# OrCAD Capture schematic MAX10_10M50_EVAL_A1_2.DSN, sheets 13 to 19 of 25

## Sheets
13 MIPI CSI-2 Rx D-PHY OV5640: size A3; title: MAX 10 FPGA (10M50) Evaluation Kit
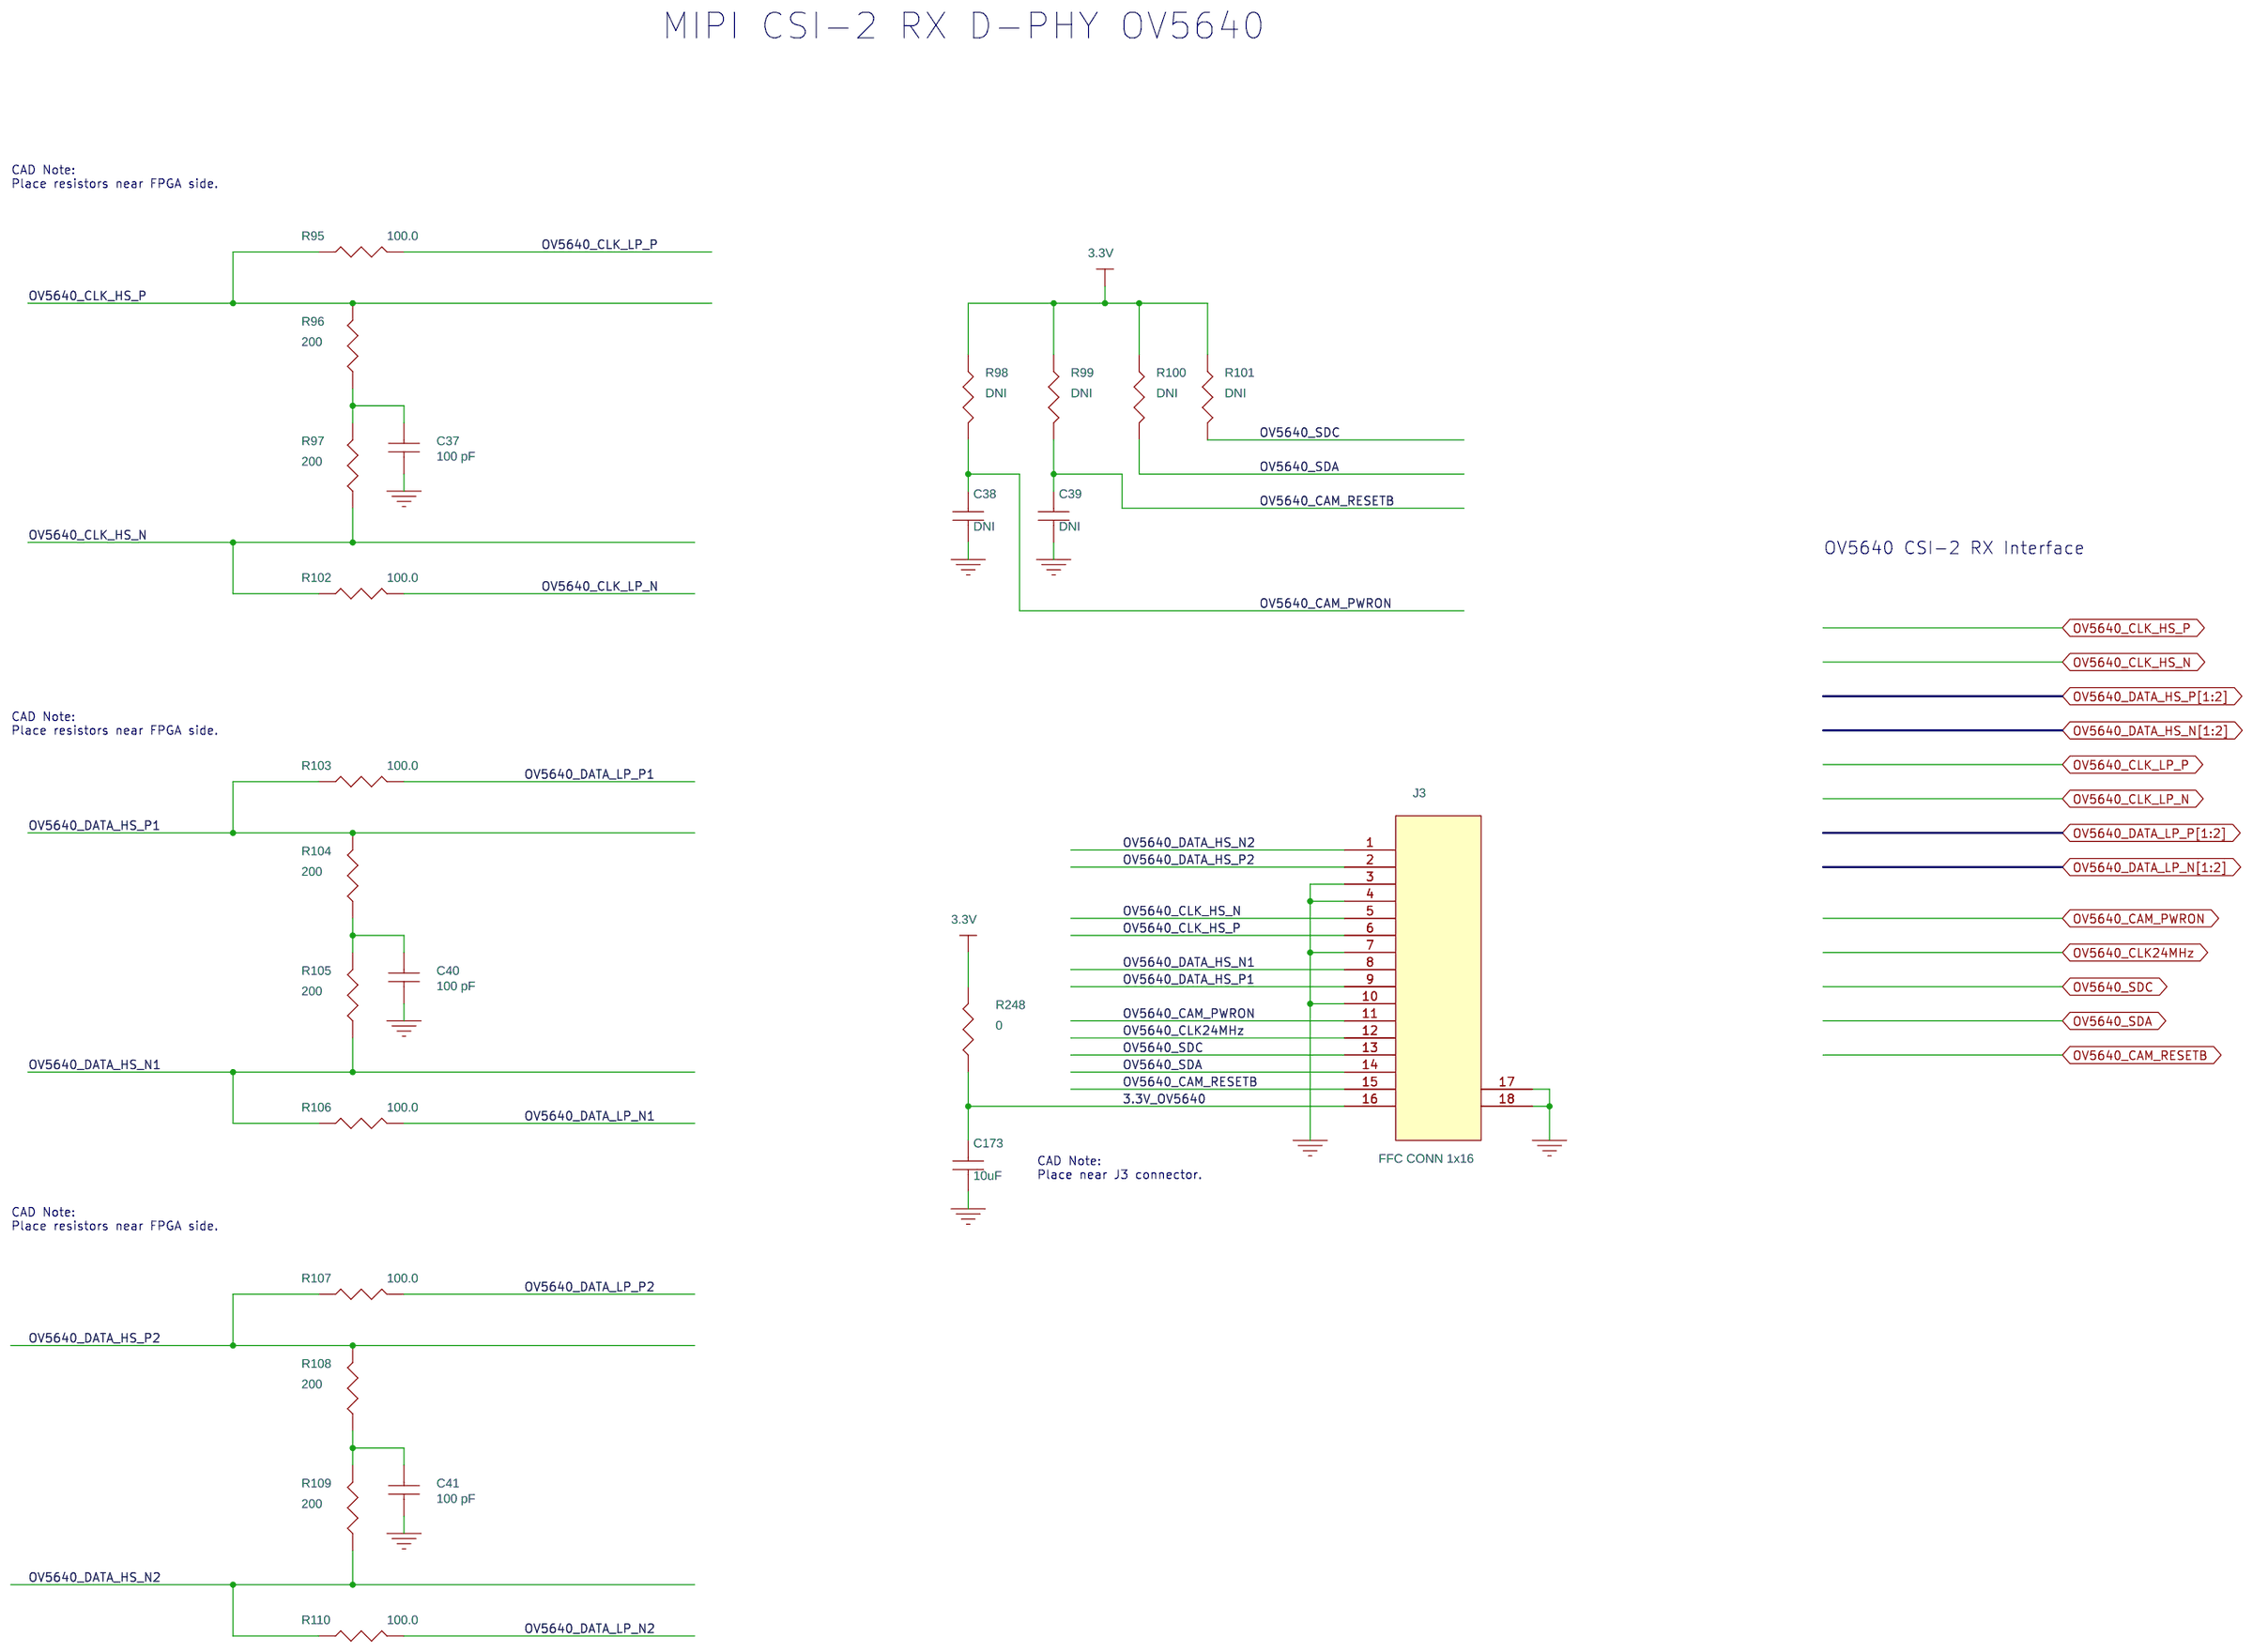
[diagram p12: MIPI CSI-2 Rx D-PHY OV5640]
14 HDMI (VIDEO ONLY): size A3
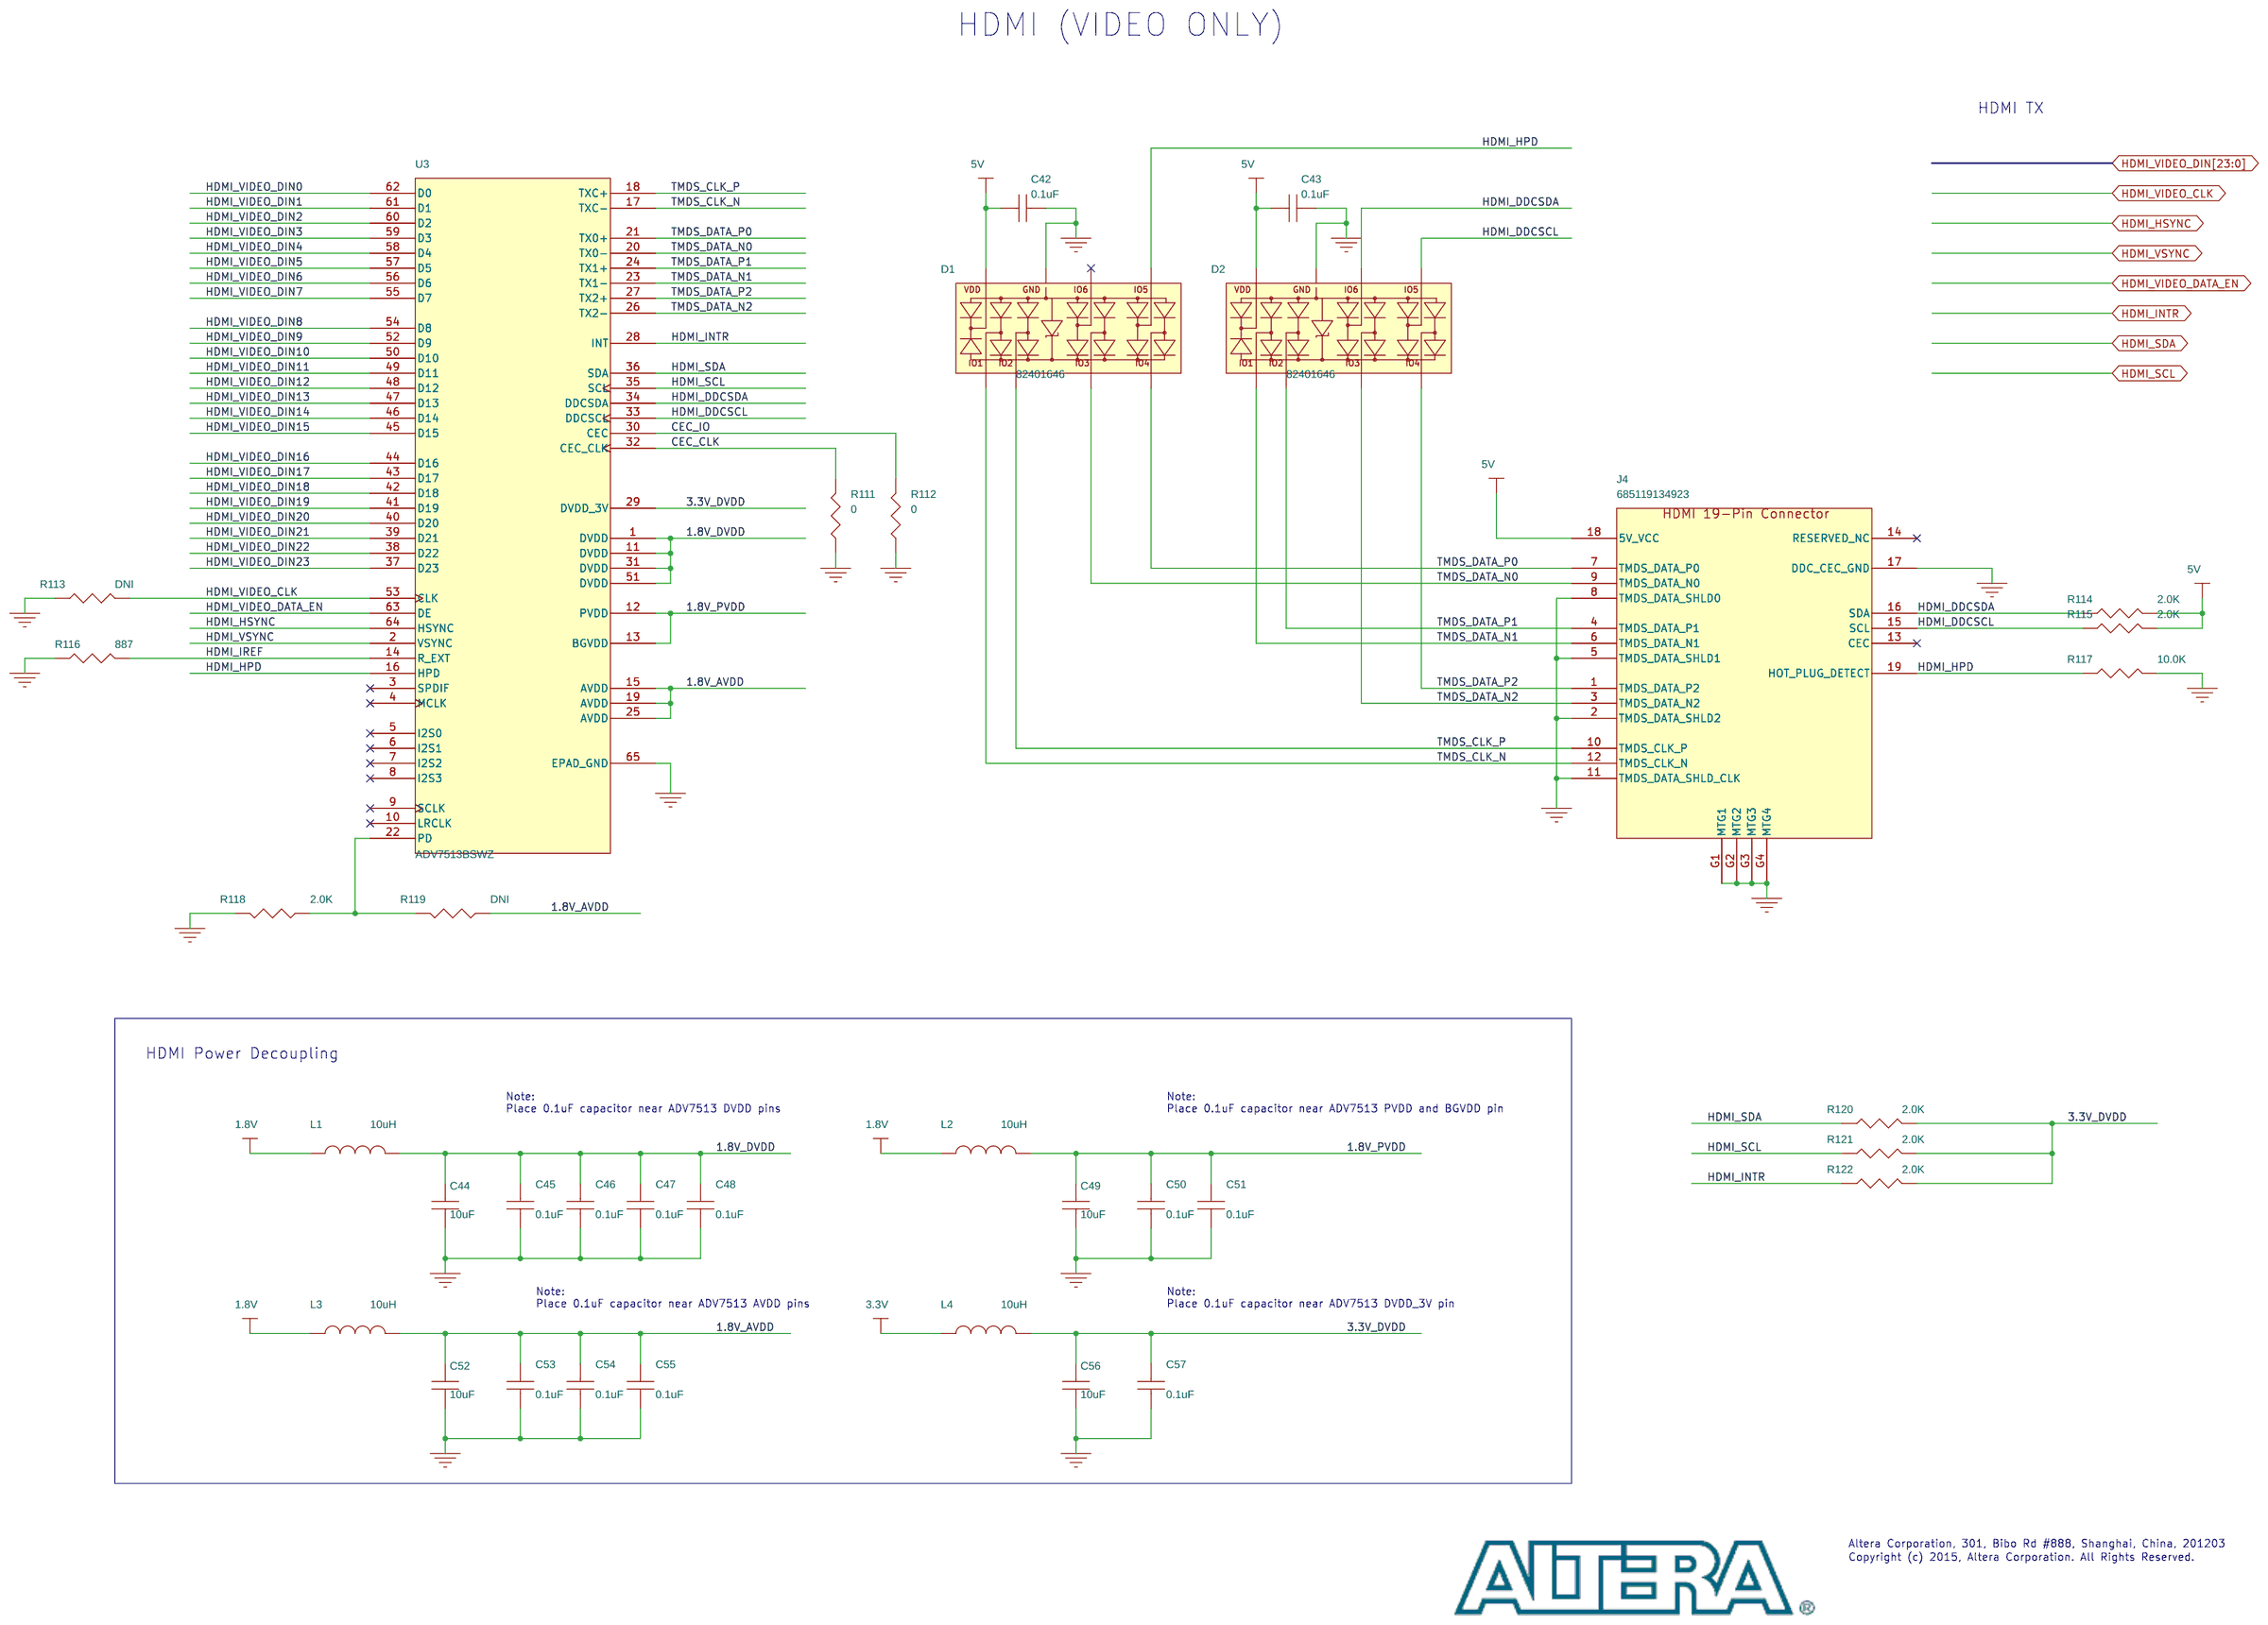
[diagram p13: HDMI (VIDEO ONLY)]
15 On-Board USB Blaster II -1: size A3
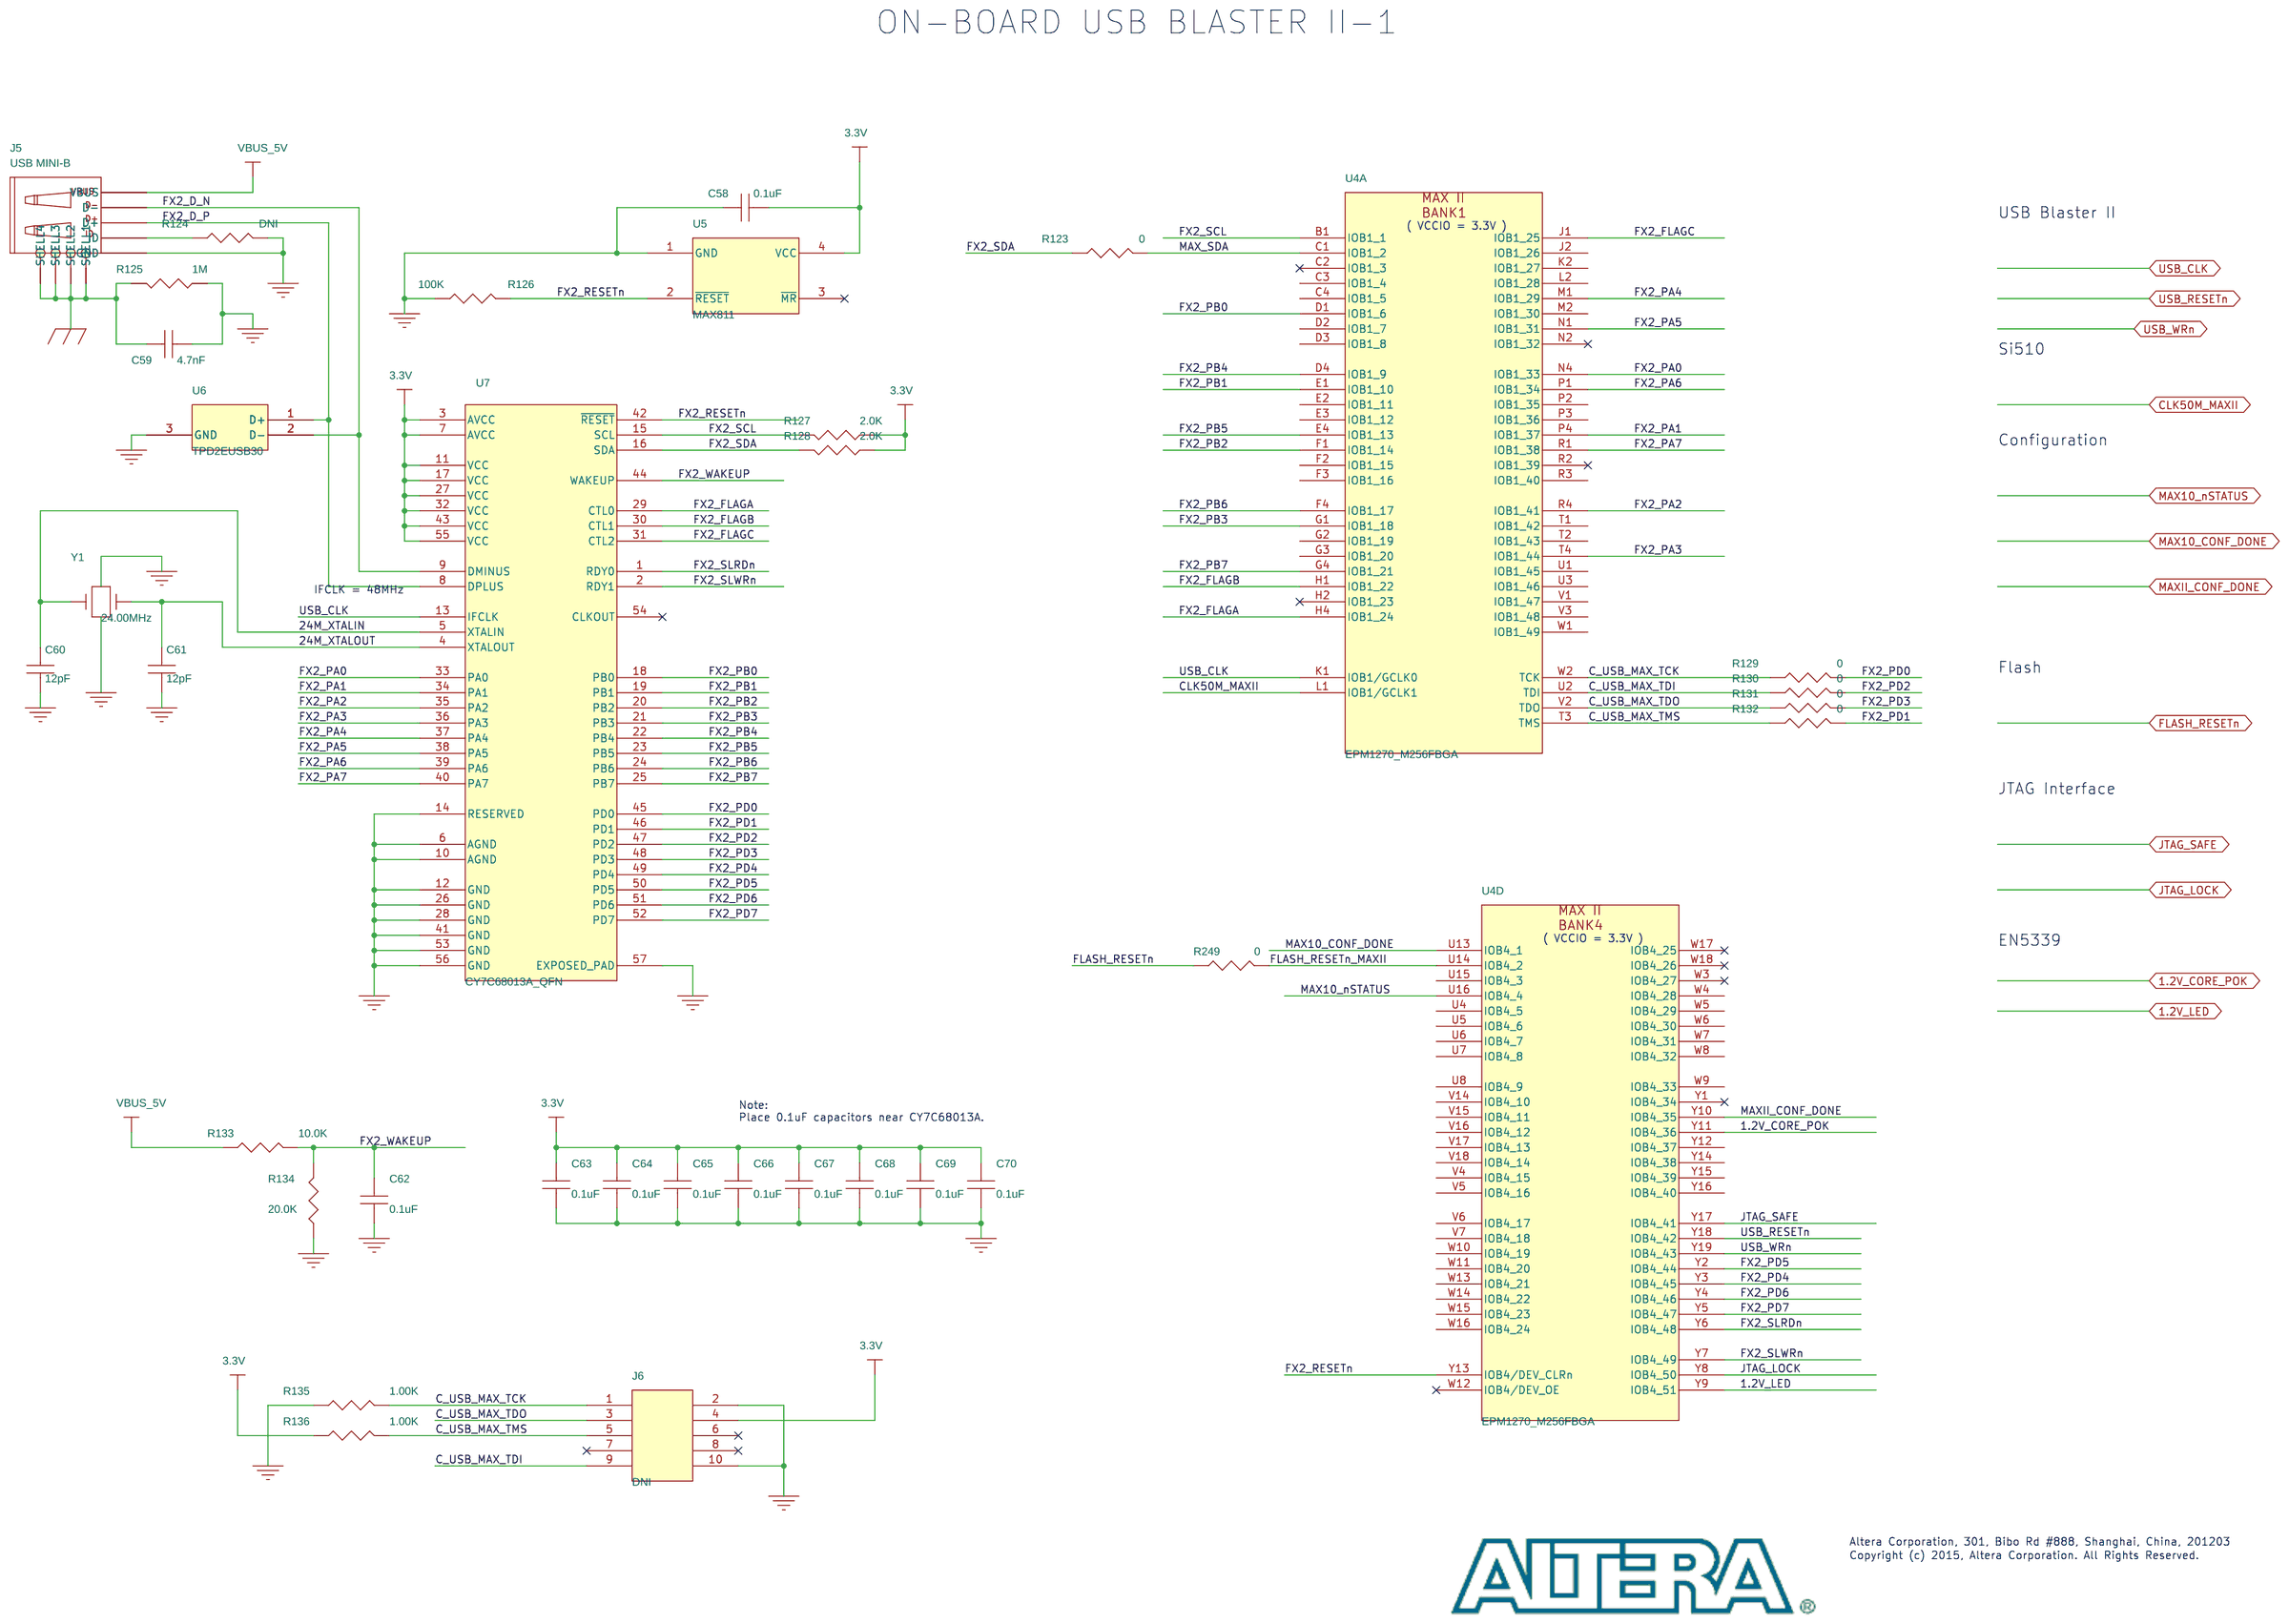
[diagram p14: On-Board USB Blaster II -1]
16 On-Board USB Blaster II-2: size A3
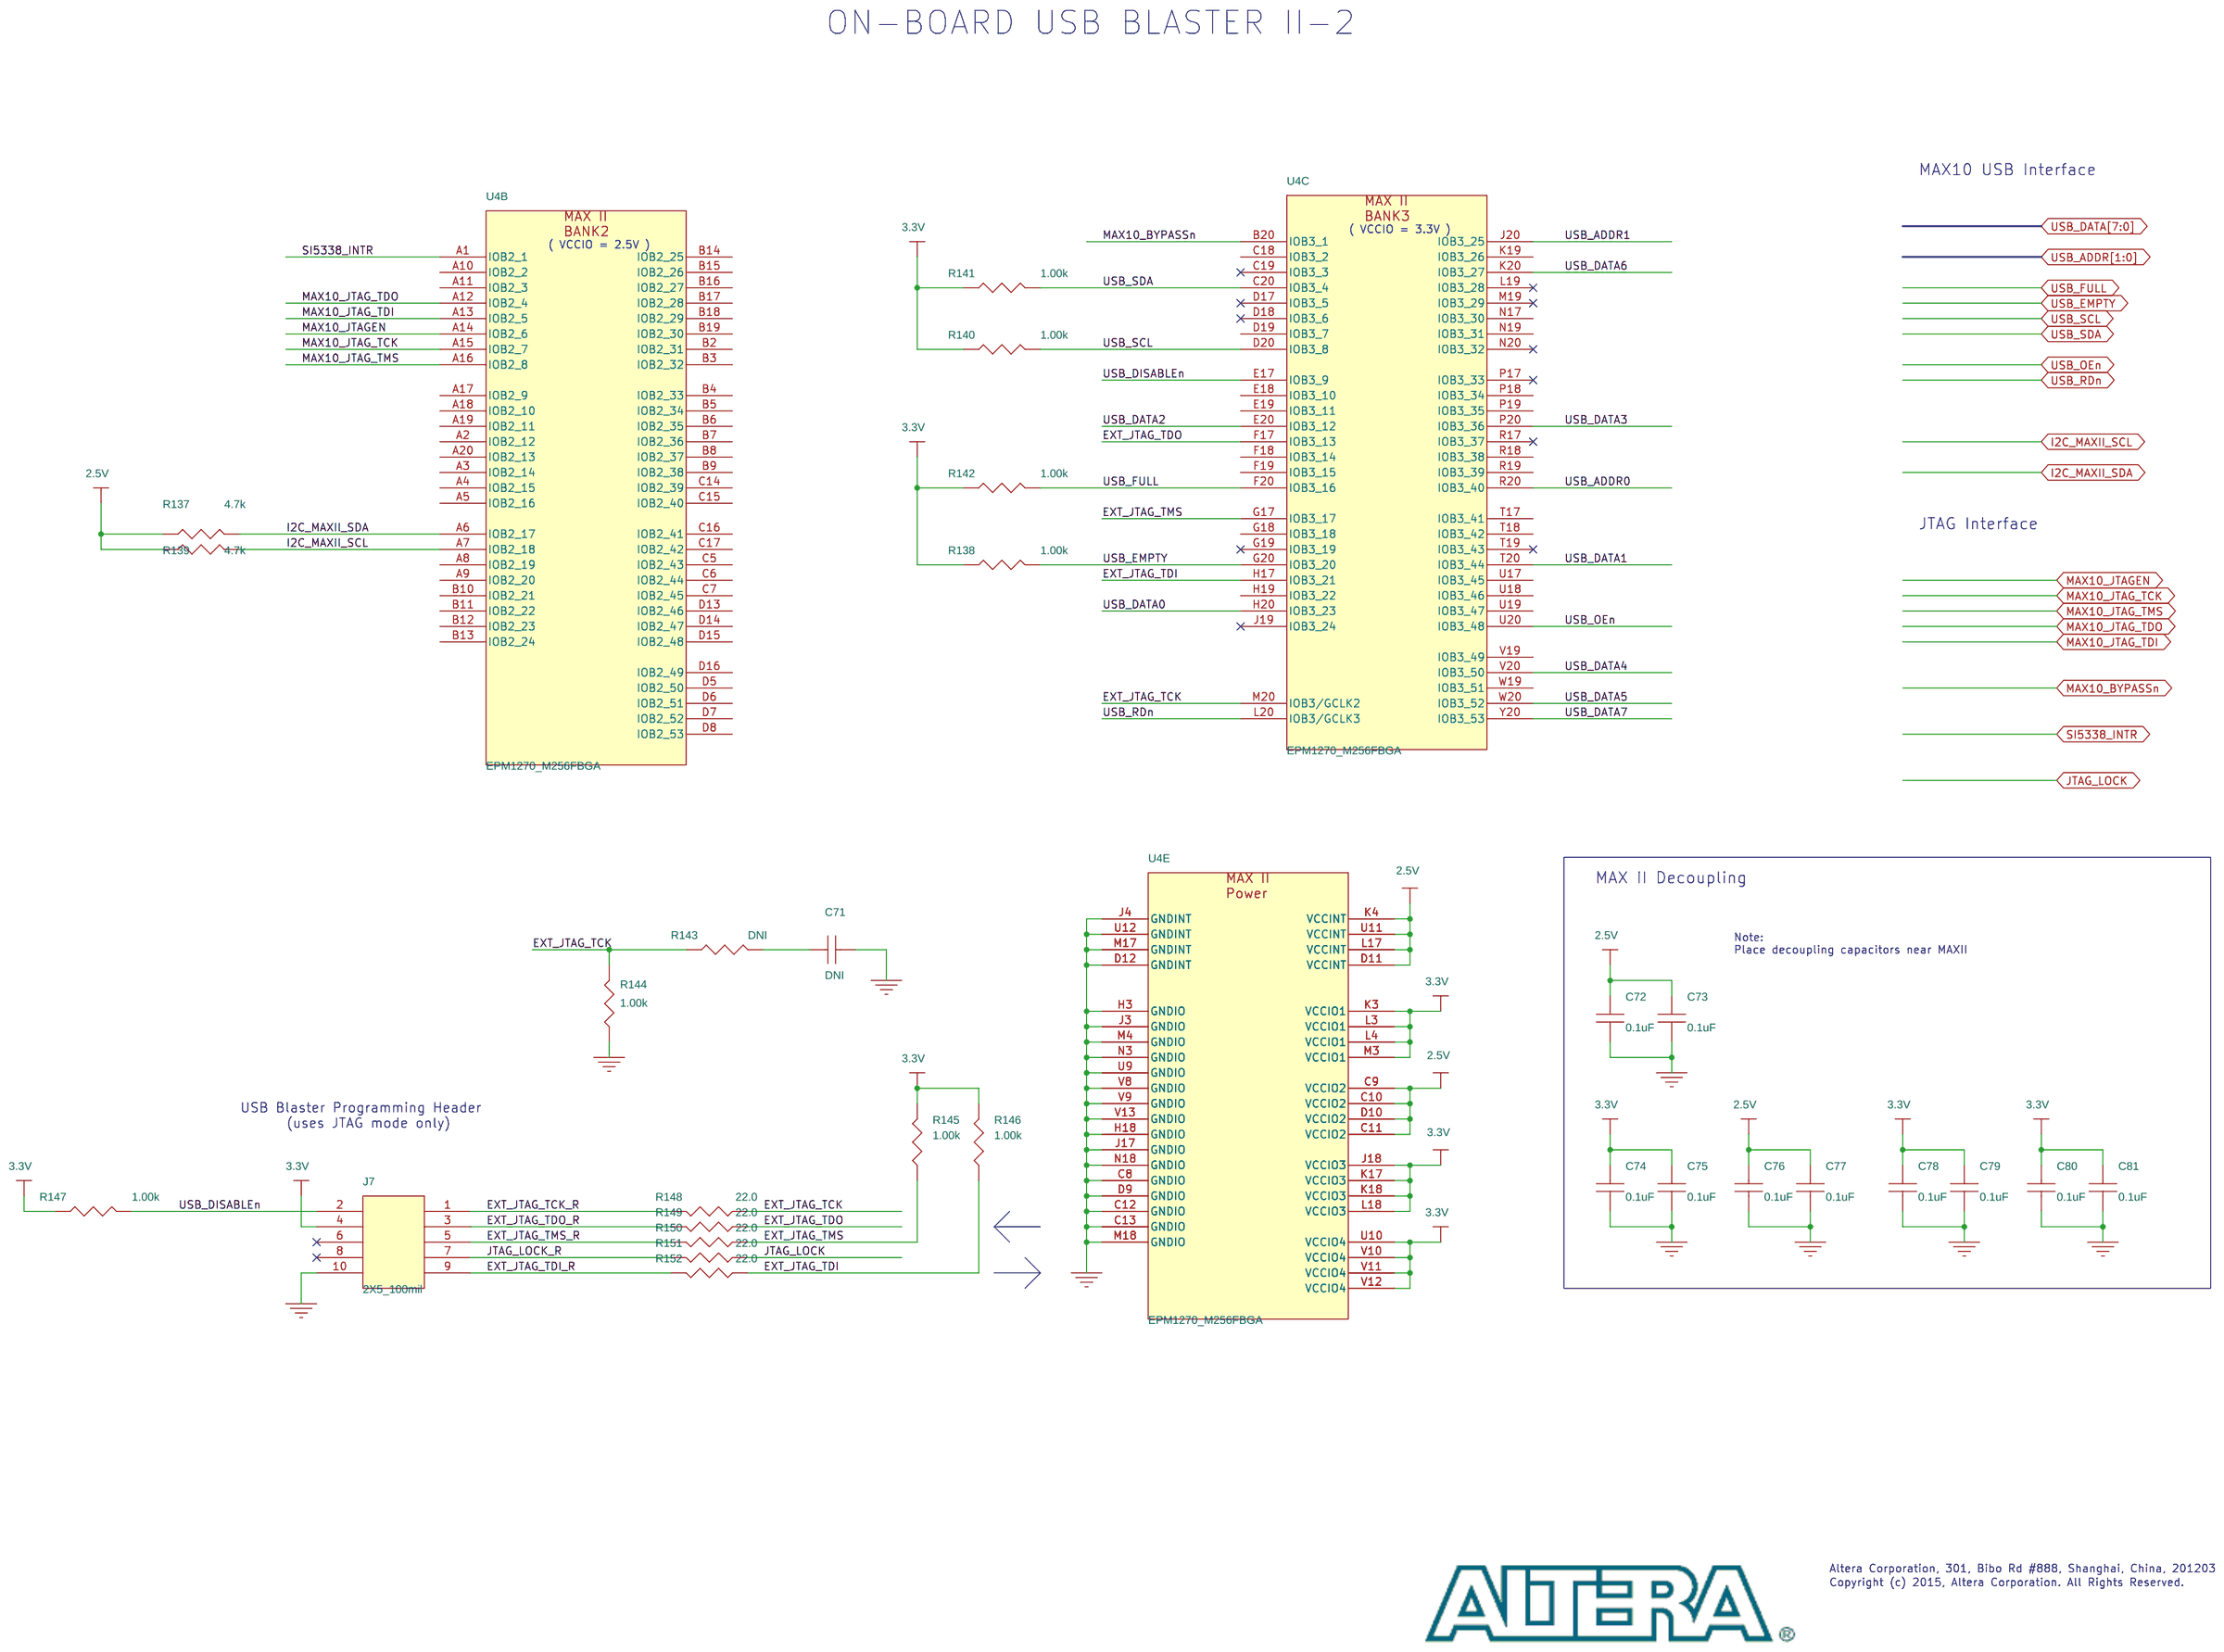
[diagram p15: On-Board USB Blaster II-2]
17 PMOD, GPIO, LVDS UserIO: size A3
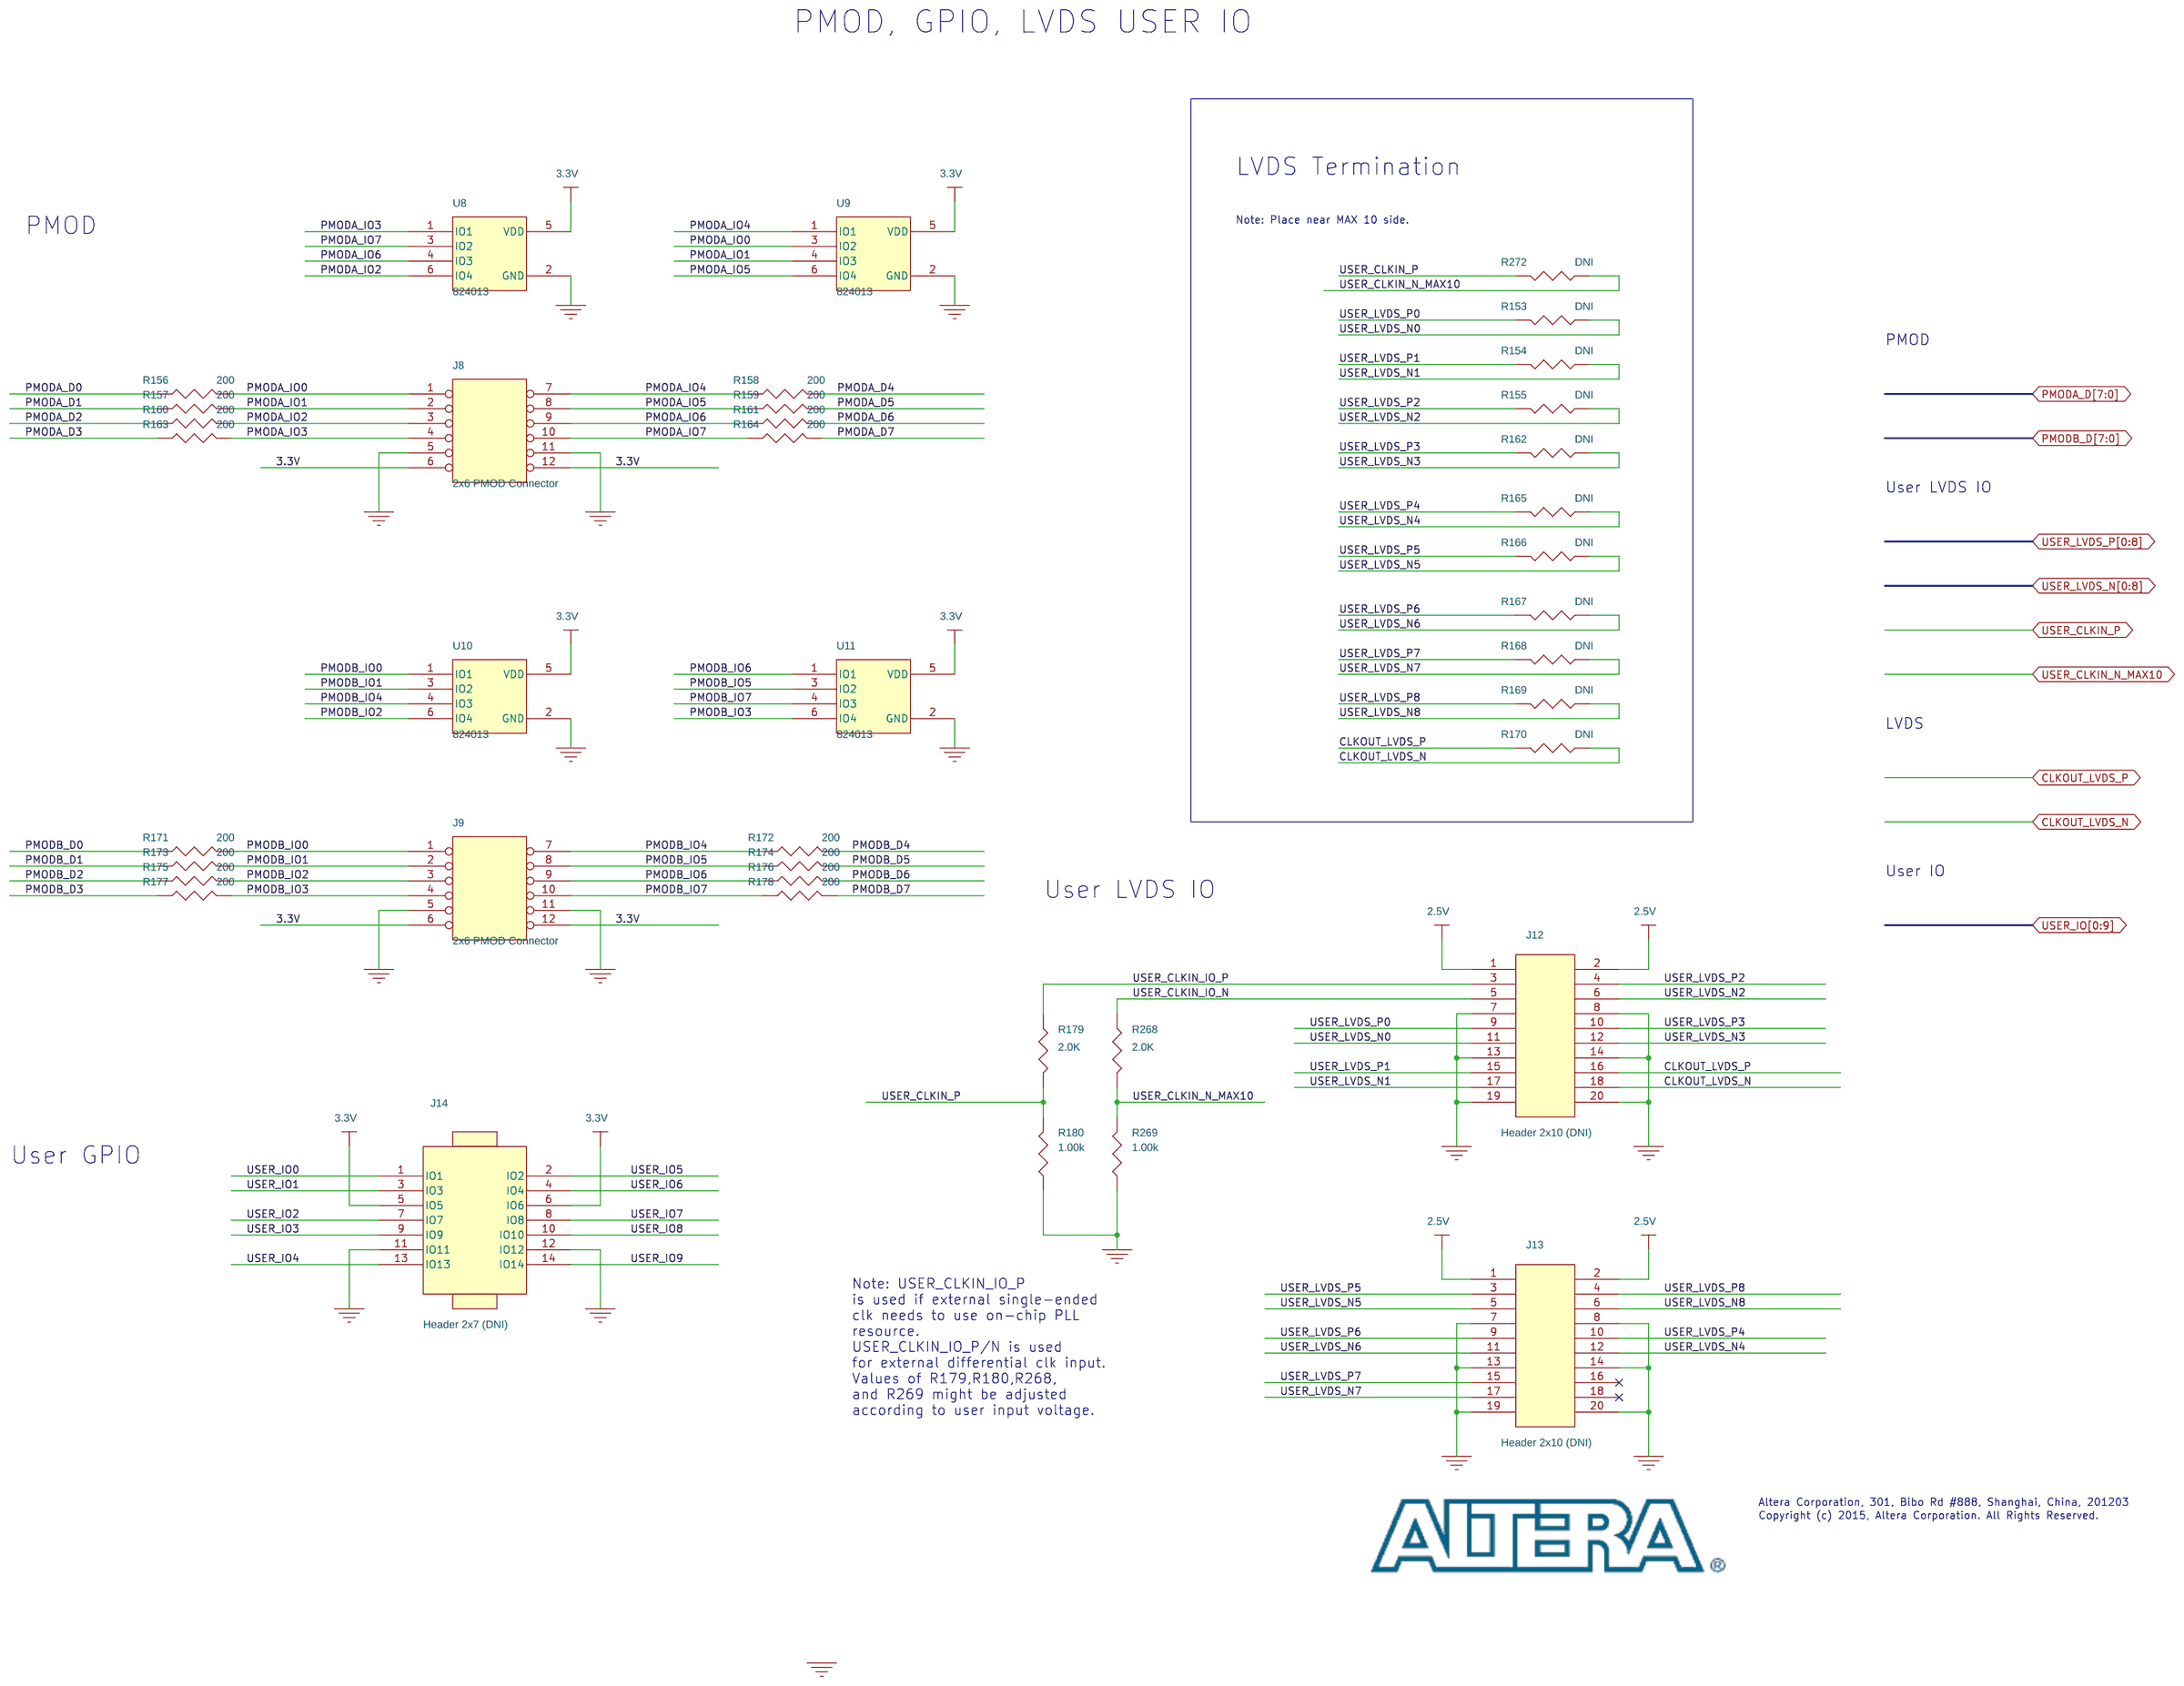
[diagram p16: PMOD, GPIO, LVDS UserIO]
18 Pushbutton, Switch, LED: size A3
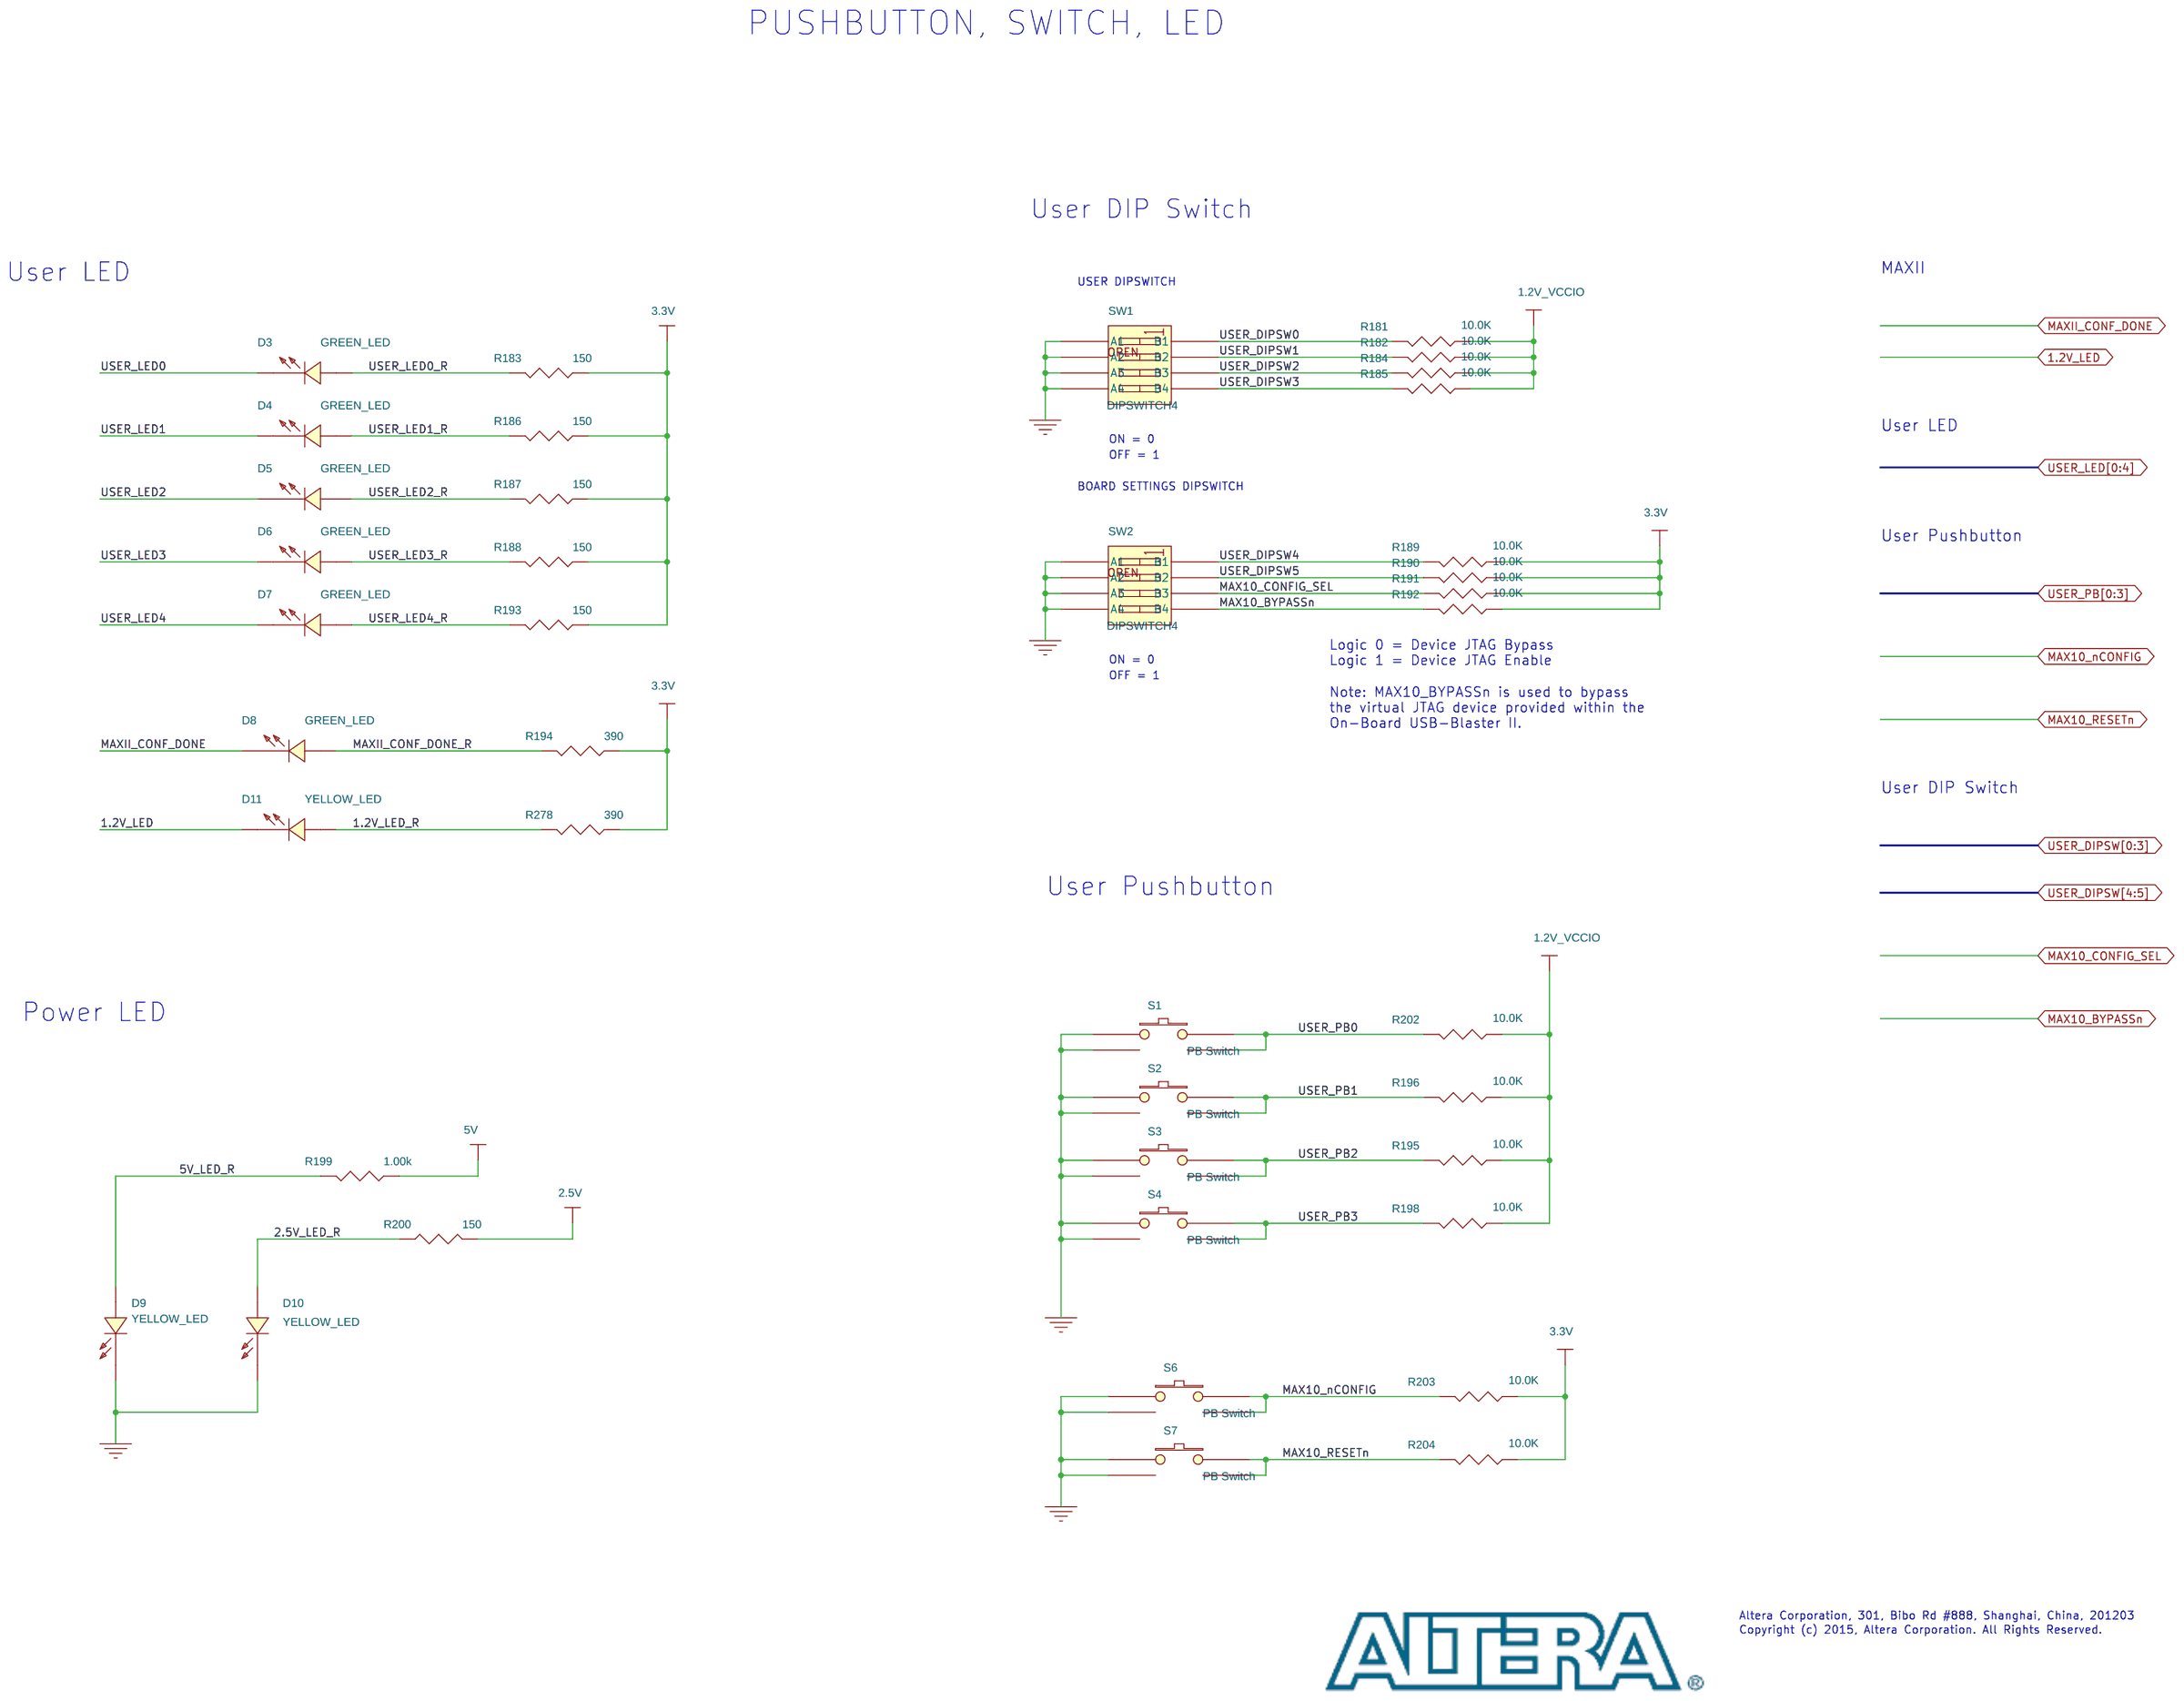
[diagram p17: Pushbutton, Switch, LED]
19 Clocking: size A3
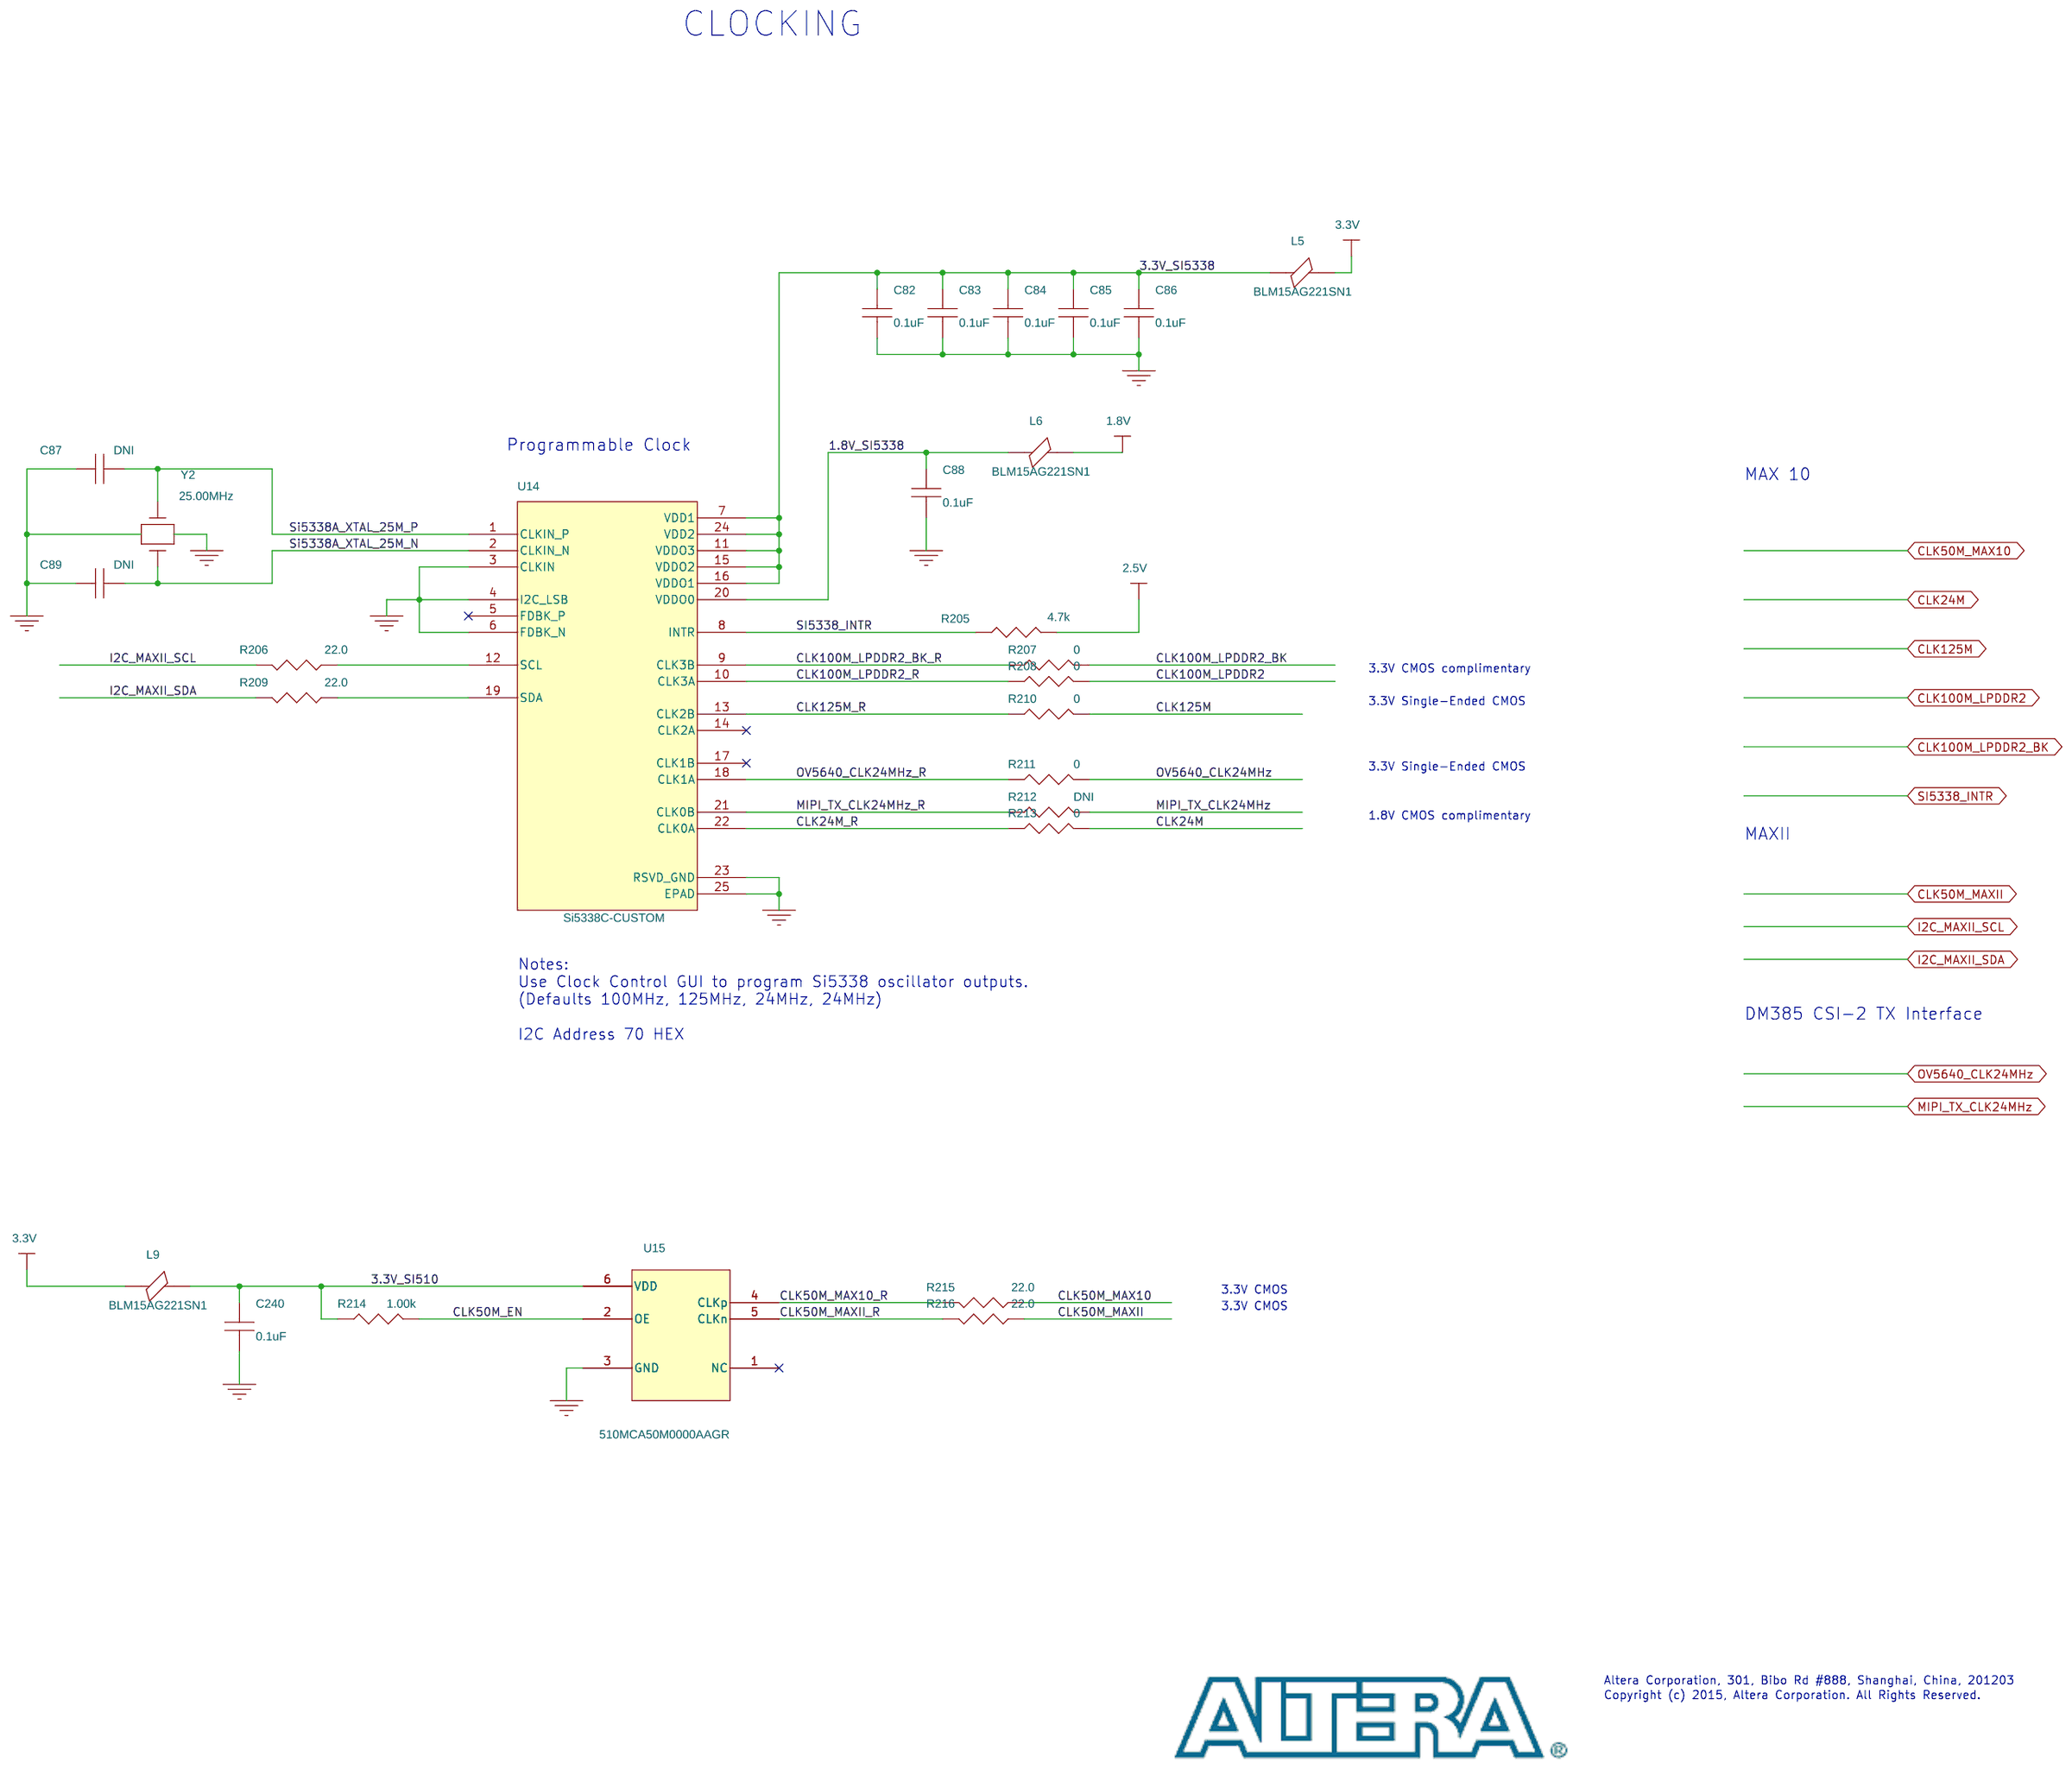
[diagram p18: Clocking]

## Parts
sheet Clocking
C82  0.1uF  [0402]
C83  0.1uF  [0402]
C84  0.1uF  [0402]
C85  0.1uF  [0402]
C86  0.1uF  [0402]
C87  DNI  [0402]
C88  0.1uF  [0402]
C89  DNI  [0402]
C240  0.1uF  [0402]
L5  BLM15AG221SN1  [0402]
L6  BLM15AG221SN1  [0402]
L9  BLM15AG221SN1  [0402]
R205  4.7k  [0402]
R206  22.0  [0402]
R207  0  [0402]
R208  0  [0402]
R209  22.0  [0402]
R210  0  [0402]
R211  0  [0402]
R212  DNI  [0402]
R213  0  [0402]
R214  1.00k  [0402]
R215  22.0  [0402]
R216  22.0  [0402]
U14  Si5338C-CUSTOM  [QFN24]
U15  510MCA50M0000AAGR  [si510]
Y2  25.00MHz  [XTAL_FA-128]
sheet HDMI (VIDEO ONLY)
C42  0.1uF  [0402]
C43  0.1uF  [0402]
C44  10uF  [0603]
C45  0.1uF  [0402]
C46  0.1uF  [0402]
C47  0.1uF  [0402]
C48  0.1uF  [0402]
C49  10uF  [0603]
C50  0.1uF  [0402]
C51  0.1uF  [0402]
C52  10uF  [0603]
C53  0.1uF  [0402]
C54  0.1uF  [0402]
C55  0.1uF  [0402]
C56  10uF  [0603]
C57  0.1uF  [0402]
D1  82401646  [wurth_msop8]
D2  82401646  [wurth_msop8]
J4  685119134923  [HDMI-19PIN]
L1  10uH  [0806]
L2  10uH  [0806]
L3  10uH  [0806]
L4  10uH  [0806]
R111  0  [0402]
R112  0  [0402]
R113  DNI  [0402]
R114  2.0K  [0402]
R115  2.0K  [0402]
R116  887  [0402]
R117  10.0K  [0402]
R118  2.0K  [0402]
R119  DNI  [0402]
R120  2.0K  [0402]
R121  2.0K  [0402]
R122  2.0K  [0402]
U3  ADV7513BSWZ  [LQFP-64]
sheet MIPI CSI-2 Rx D-PHY OV5640
C37  100 pF  [0402]
C38  DNI  [C0402_BGA]
C39  DNI  [C0402_BGA]
C40  100 pF  [0402]
C41  100 pF  [0402]
C173  10uF  [0603]
J3  FFC CONN 1x16  [68711614522]
R95  100.0  [0402]
R96  200  [0402]
R97  200  [0402]
R98  DNI  [0402]
R99  DNI  [0402]
R100  DNI  [0402]
R101  DNI  [0402]
R102  100.0  [0402]
R103  100.0  [0402]
R104  200  [0402]
R105  200  [0402]
R106  100.0  [0402]
R107  100.0  [0402]
R108  200  [0402]
R109  200  [0402]
R110  100.0  [0402]
R248  0  [0402]
sheet On-Board USB Blaster II -1
C58  0.1uF  [0402]
C59  4.7nF  [0402]
C60  12pF  [0402]
C61  12pF  [0402]
C62  0.1uF  [0402]
C63  0.1uF  [0402]
C64  0.1uF  [0402]
C65  0.1uF  [0402]
C66  0.1uF  [0402]
C67  0.1uF  [0402]
C68  0.1uF  [0402]
C69  0.1uF  [0402]
C70  0.1uF  [0402]
J5  USB MINI-B  [Wurth_USB_MINI-B]
J6  DNI  [hdr2x5_100mil_smt]
R123  0  [0402]
R124  DNI  [0402]
R125  1M  [0402]
R126  100K  [0402]
R127  2.0K  [0402]
R128  2.0K  [0402]
R129  0  [0402]
R130  0  [0402]
R131  0  [0402]
R132  0  [0402]
R133  10.0K  [0402]
R134  20.0K  [0402]
R135  1.00K  [0402]
R136  1.00K  [0402]
R249  0  [0402]
U5  MAX811  [SOT-143]
U6  TPD2EUSB30  [DRT]
U7  CY7C68013A_QFN  [QFN56]
Y1  24.00MHz  [XTAL_FA-128]
sheet On-Board USB Blaster II-2
C71  DNI  [0402]
C72  0.1uF  [0402]
C73  0.1uF  [0402]
C74  0.1uF  [0402]
C75  0.1uF  [0402]
C76  0.1uF  [0402]
C77  0.1uF  [0402]
C78  0.1uF  [0402]
C79  0.1uF  [0402]
C80  0.1uF  [0402]
C81  0.1uF  [0402]
J7  2X5_100mil  [hdr2x5_100mil_smt]
R137  4.7k  [0402]
R138  1.00k  [0402]
R139  4.7k  [0402]
R140  1.00k  [0402]
R141  1.00k  [0402]
R142  1.00k  [0402]
R143  DNI  [0402]
R144  1.00k  [0402]
R145  1.00k  [0402]
R146  1.00k  [0402]
R147  1.00k  [0402]
R148  22.0  [0402]
R149  22.0  [0402]
R150  22.0  [0402]
R151  22.0  [0402]
R152  22.0  [0402]
U4  EPM1270_M256FBGA  [M256]  (sections A,B,C,D,E)
sheet PMOD, GPIO, LVDS UserIO
J8  2x6 PMOD Connector  [HDR2X6_100MIL]
J9  2x6 PMOD Connector  [HDR2X6_100MIL]
J12  Header 2x10 (DNI)  [10-89-1201]
J13  Header 2x10 (DNI)  [10-89-1201]
J14  Header 2x7 (DNI)  [10-89-1141]
R153  DNI  [0402]
R154  DNI  [0402]
R155  DNI  [0402]
R156  200  [0402]
R157  200  [0402]
R158  200  [0402]
R159  200  [0402]
R160  200  [0402]
R161  200  [0402]
R162  DNI  [0402]
R163  200  [0402]
R164  200  [0402]
R165  DNI  [0402]
R166  DNI  [0402]
R167  DNI  [0402]
R168  DNI  [0402]
R169  DNI  [0402]
R170  DNI  [0402]
R171  200  [0402]
R172  200  [0402]
R173  200  [0402]
R174  200  [0402]
R175  200  [0402]
R176  200  [0402]
R177  200  [0402]
R178  200  [0402]
R179  2.0K  [0402]
R180  1.00k  [0402]
R268  2.0K  [0402]
R269  1.00k  [0402]
R272  DNI  [0402]
U8  824013  [SOT23-6L]
U9  824013  [SOT23-6L]
U10  824013  [SOT23-6L]
U11  824013  [SOT23-6L]
sheet Pushbutton, Switch, LED
D3  GREEN_LED  [LED_0603]
D4  GREEN_LED  [LED_0603]
D5  GREEN_LED  [LED_0603]
D6  GREEN_LED  [LED_0603]
D7  GREEN_LED  [LED_0603]
D8  GREEN_LED  [LED_0603]
D9  YELLOW_LED  [LED_0603]
D10  YELLOW_LED  [LED_0603]
D11  YELLOW_LED  [LED_0603]
R181  10.0K  [0402]
R182  10.0K  [0402]
R183  150  [0402]
R184  10.0K  [0402]
R185  10.0K  [0402]
R186  150  [0402]
R187  150  [0402]
R188  150  [0402]
R189  10.0K  [0402]
R190  10.0K  [0402]
R191  10.0K  [0402]
R192  10.0K  [0402]
R193  150  [0402]
R194  390  [0402]
R195  10.0K  [0402]
R196  10.0K  [0402]
R198  10.0K  [0402]
R199  1.00k  [0402]
R200  150  [0402]
R202  10.0K  [0402]
R203  10.0K  [0402]
R204  10.0K  [0402]
R278  390  [0402]
S1  PB Switch  [pushbutton_smt]
S2  PB Switch  [pushbutton_smt]
S3  PB Switch  [pushbutton_smt]
S4  PB Switch  [pushbutton_smt]
S6  PB Switch  [pushbutton_smt]
S7  PB Switch  [pushbutton_smt]
SW1  DIPSWITCH4  [DIPSWITCH_SMT_QUAD]
SW2  DIPSWITCH4  [DIPSWITCH_SMT_QUAD]

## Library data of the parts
C42 C43 C45-C48 C50 C51 C53-C55 C57 C58 C62-C86 C88 C240 = Cap_0.1UF_+_-10%_10V_0402
C87 C89 = Cap_18PF_5%_50V_0402
L5 L6 L9 = IND_Ferrite_0402_300mA_220
R137 R139 R205 = RES_4.7k_OHM_5%_1_16W_0402: RES - 4.7K OHMS, 5%, 1/16W,0402
R148-R152 R206 R209 R215 R216 = RESISTOR: RES - 22.0 OHM, 1/16W, 1%, 0402 SMD; Item Num: P02-16269R; Lead Free Status: Yes; Manufacturer: Panasonic; Manufacturer Part Num: ERJ-2RKF22R0X; Num Pins: 2; Part Class: Resistors; Price: 0
R111 R112 R123 R129-R132 R207 R208 R210 R211 R213 R248 R249 = RESISTOR: RES ZERO OHM 1/16W 5% 0402 SMD; Altera Part No.: P02-14020R; Item Num: P02-14020R; Lead Free Status: No; Manufacturer: Panasonic; Manufacturer Part Num: ERJ-2GE0R00X; Num Pins: 2; Part Class: RESISTORS; RoHS Compliant: Yes; Tolerance: 5%
R124 R212 = RESISTOR: RES ZERO OHM 1/16W 5% 0402 SMD; Altera Part No.: P02-14020R; Item Num: P02-14020R; Lead Free Status: No; Manufacturer: Panasonic; Manufacturer Part Num: ERJ-2GE0R00X; Num Pins: 2; Part Class: RESISTORS; Price: 0; RoHS Compliant: Yes; Tolerance: 5%
R138 R140-R142 R144-R147 R180 R199 R214 R269 = RESISTOR: RES,1.00K OHMS,1.0%,1/16W,0402; Item Num: P02-11372R; Lead Free Status: No; Manufacturer: Panasonic; Manufacturer Part Num: ERJ-2RKF1001X; Num Pins: 2; Part Class: Resistors
U14 = Clock_Gen,_Si5338A_CUSTOM,_A5SK: IC - PROG,1.8V, 3.3V CMOS QUAD CLOCK, 24M, 24M, 125M, 100M DEFAULTS, I2C 70; Item Num: P13-27236R; Manufacturer Part Num: Si5338C-B04601-GM
U15 = Si510-DualCMOS: OSC - 50MHZ, +/-30PPM, 3.3V, DUAL CMOS (IN PHASE), CRYSTAL OSCILLATOR, SMD; Item Num: P13-27235R; Manufacturer: Silicon Labs
Y2 = XTAL_25MHz_30PPM_18pF_mini
C44 C49 C52 C56 C173 = CAP: CAP - CERAMIC, 10UF, 6.3V, +/-20%, X5R, 0603 SMD; AGILE_LINK: http://sj-agile9app/Agile/PLMServlet?action=OpenEmailObject&classid=10000&objid=260383822; Item Num: P03-16323R; LIFECYCLE_PHASE: Active; Lead Free Status: Lead Free; MFR_LIFECYCLE: Active; Manufacturer: Panasonic; Manufacturer Part Num: ECJ-1VB0J106M; Num Pins: 2; PART_SUBCLASS: CAPACITORS; RATED_VOLTAGE: 6.3V; RoHS Compliant: RoHS Compliant; TOLERANCE: +/-20%
D1 D2 = 82401646: DIODE - ULTRA LOW CAPACITANCE ESD ARRAY, 0.3PF IO TO GND, 0.05PF IO TO IO, MSOP-8L; Item Num: P08-20757R; Lead Free Status: Yes; Manufacturer: Wurth; Num Pins: 8; RoHS Compliant: Yes
J4 = HDMI_19-Pin_Receptacle: CONN-HDMI RECEPTABLE; Item Num: P23-38479R; Manufacturer: Wurth Elektronik
L1-L4 = IND_10uH_245mA_0.82ohm_0806_SMD
R113 = R: RES, 49.9 OHMS, 1%, 1/16W, 0402; Item Num: P02-14101R; Lead Free Status: Yes; Manufacturer: NIC Components Corp.; Manufacturer Part Num: NRC04F49R9TRF; Num Pins: 2; Part Class: Resistors; Price: 0
R114 R115 R118-R122 R127 R128 R179 R268 = RES_2.0K_OHM_1_16W_1%_0402_SMD
R116 = R: RES - 887 OHM, 1%, 1/16W, 0402 SMD; AGILE_LINK: http://sj-agile9app/Agile/PLMServlet?action=OpenEmailObject&classid=10000&objid=259725586; Item Num: P02-15629R; LIFECYCLE_PHASE: Preliminary; Lead Free Status: Lead Free; MFR_LIFECYCLE: Active; Manufacturer: Panasonic; Manufacturer Part Num: ERJ-2RKF8870x; Num Pins: 2; PART_SUBCLASS: RESISTORS; RoHS Compliant: RoHS Compliant
R117 R133 R181 R182 R184 R185 R189-R192 R195 R196 R198 R202-R204 = RESISTOR: RES,10.0K OHMS,1.0%,1/16W, 0402; AGILE_LINK: http://sj-agile9app/Agile/PLMServlet?action=OpenEmailObject&classid=10000&objid=146548997; Item Num: P02-11364R; LIFECYCLE_PHASE: Active; Lead Free Status: No; MFR_LIFECYCLE: Active; Manufacturer: Panasonic; Manufacturer Part Num: ERJ-2RKF1002X; Num Pins: 2; PART_SUBCLASS: RESISTORS; POWER: 1/16W; RoHS Compliant: Yes; TOLERANCE: +/-1%
U3 = ADV7513BSWZ: IC TX HDMI 165MHZ 64LQFP; Item Num: P01-17910R; Manufacturer: Analog Devices Inc
C37 C40 C41 = Cap_0.1UF_+_-10%_10V_0402: CAP, CERAMIC, 100PF, 10%, 50V, 0402, X7R; Item Num: P03-15133R; Manufacturer Part Num: ECJ-0EB1H101K
C38 C39 = CAP_1.0UF_10%_10V_0402
J3 = FFC_CONN_0: CONN FPC HORIZONTAL 16POS 0.5mm SMT ZIF, Bottom Contact; Item Num: P23-38696R; Manufacturer: Wurth Electronics
R95 R102 R103 R106 R107 R110 R153-R155 R162 R165-R170 R272 = RES_100_OHM_1.0%_1_16W_0402: RES,100OHMS, 1.0%, 1/16W, 0402
R96 R97 R104 R105 R108 R109 R156-R161 R163 R164 R171-R178 = RESISTOR: RES,200 OHMS,1.0%,1/16W,0402; Item Num: P02-10716R; Lead Free Status: Yes; Manufacturer: Panasonic; Manufacturer Part Num: ERJ-2RKF2000X; Num Pins: 2; Part Class: Resistors; Price: 0; RoHS Compliant: Yes
R98-R101 = RES_2.0K_OHM_1_16W_1%_0402_SMD: RES 2.2K OHM 1/16W 5% 0402 SMD; Item Num: P02-14027R; Manufacturer Part Num: ERJ-2GEJ222X
C59 = Cap_4.7nF_10%_50V_0402: CAP 4700PF 25V CERAMIC 0402 SMD ±10% X7R; Item Num: P03-16476R; Manufacturer: Panasonic; Manufacturer Part Num: ECJ-0EB1E472K
C60 C61 = CAP: CAP - 12PF, 50V, +/-5%, CERAMIC, 0402 SMD; AGILE_LINK: http://sj-agile9app/Agile/PLMServlet?action=OpenEmailObject&classid=10000&objid=257385742; Item Num: P03-15352R; LIFECYCLE_PHASE: Active; Lead Free Status: Lead Free; MFR_LIFECYCLE: Active; Manufacturer: Panasonic; Manufacturer Part Num: ECJ-0EC1H120J; Num Pins: 2; PART_SUBCLASS: CAPACITORS; RATED_VOLTAGE: 50V; RoHS Compliant: RoHS Compliant; TOLERANCE: +/-5%
J5 = USB_MINI-B: CONN - MINI USB 5POS HORIZ T/H; Item Num: P23-38638R; Manufacturer: Wurth Elektronik; Manufacturer Part Num: 651 005 136 521
J6 J7 = 2x5: CONN - CONN HEADER VERT DUAL 10POS 2.54MM; Item Num: P23-38640R; Lead Free Status: No; Manufacturer: Wurth Elektronik; Manufacturer Part Num: 61001021121; Num Pins: 10; Part Class: Connectors; Price: 0; RoHS Compliant: Yes
R125 = RESISTOR: RES 1.00M OHM 1/16W 1% 0402 SMD; Item Num: P02-14034R; LIFECYCLE_PHASE: Active; Lead Free Status: Lead Free; MFR_LIFECYCLE: Active; Manufacturer: Panasonic; Manufacturer Part Num: ERJ-2RKF1004X; Num Pins: 2; Package: SMD; RoHS Compliant: RoHS Compliant; TOLERANCE: +/-1%
R126 = RESISTOR: RES,100K OHMS,1.0%,1/16W,0402; Item Num: P02-11386R; Lead Free Status: No; Manufacturer: Panasonic; Manufacturer Part Num: ERJ-2RKF1003X; Num Pins: 2; Part Class: Resistors; Price: 0; RoHS Compliant: Yes
R134 = RESISTOR: RES 20.0K OHM 1/16W 1% 0402 SMD; Item Num: P02-14071R; Lead Free Status: Yes; Manufacturer: Panasonic; Manufacturer Part Num: ERJ-2RKF2002X; Num Pins: 2; Part Class: RESISTORS; RoHS Compliant: Yes
R135 R136 = RESISTOR: RES,1.00K OHMS,1.0%,1/16W,0402; Item Num: P02-11372R; Lead Free Status: No; Manufacturer: Panasonic; Manufacturer Part Num: ERJ-2RKF1001X; Num Pins: 2; Part Class: Resistors; Price: 0
U5 = MAX811: IC - MPU V-MONITOR 2.93V, RESET/POWER-ON RESET, SOT143-4; Item Num: P01-17588R; Lead Free Status: Yes; Manufacturer: Maxim Integrated Products; Manufacturer Part Num: MAX811SEUS+T; Num Pins: 4; Part Class: ICs; RoHS Compliant: Yes
U6 = TPD2EUSB30: DIODE - FULL SPEED USB ESD SOLUTION, 2CH, SOT3; Item Num: P08-20777R; Lead Free Status: Yes; MFR_LIFECYCLE: Active; Manufacturer: Texas Instruments; Manufacturer Part Num: TPD2EUSB30DRxx; Num Pins: 3; Part Class: ICS; RoHS Compliant: Yes
U7 = CY7C68013A_56QFN: IC - EZ-USB FX2LP Microcontroller 400KHz, 56-QFN, 3.3V; Item Num: P01-17739R; Lead Free Status: Yes; Manufacturer: Cypress; Manufacturer Part Num: CY7C68013A-56LTXCx; Num Pins: 57; Part Class: ICs; RoHS Compliant: Yes
Y1 = CRYSTAL_SM_13: CRYSTAL - MINI XTL, 24.00 MHZ, +/-50PPM, +/-30PPM-20~75C, 12PF, 2.0mm x 1.6mm SMD; Item Num: P07-19648R; Lead Free Status: Yes; MFR_LIFECYCLE: Active; Manufacturer: Epson Toyocom; Manufacturer Part Num: FA-128 24.0000MB-W:; Num Pins: 4; RoHS Compliant: Yes
R143 = RESISTOR: RES,10.0K OHMS,1.0%,1/16W, 0402; AGILE_LINK: http://sj-agile9app/Agile/PLMServlet?action=OpenEmailObject&classid=10000&objid=146548997; Item Num: P02-11364R; LIFECYCLE_PHASE: Active; Lead Free Status: No; MFR_LIFECYCLE: Active; Manufacturer: Panasonic; Manufacturer Part Num: ERJ-2RKF1002X; Num Pins: 2; PART_SUBCLASS: RESISTORS; POWER: 1/16W; RESISTANCE: 10.0K; RoHS Compliant: Yes; TOLERANCE: +/-1%
U4 = EPM1270M256_2: IC - MAX II EPM1270 256-MBGA, 2.5V/3.3V VCCINT; Item Num: P01-17848R; LIFECYCLE_PHASE: Preliminary; Lead Free Status: Lead Free; MFR_LIFECYCLE: Active; Manufacturer: Altera Corporation; Manufacturer Part Num: EPM1270M256C4N; Num Pins: 256; PART_SUBCLASS: ICS; RoHS Compliant: RoHS Compliant
J8 J9 = 2x6_PMOD: CONN - HEADER 2X6CONN HEADER - 12 POS, 2.54MM ANGLED DUAL SOCKET HEADER WR-PHD, 0.1", TH LEADS 0.1", LEAD LENGTH 0.230"; Item Num: P23-38635R; Manufacturer: Wurth Elektronik; Manufacturer Part Num: 613012243121
J12 J13 = 2x10: CONN - CONN HEADER VERT DUAL 20POS 2.54; Item Num: P23-38639R; Manufacturer: Wurth Elektronik; Manufacturer Part Num: 61302021121; Mfr Code: MOL; Num Pins: 20; Part Class: CON; RoHS Compliant: 1
J14 = Header_3: CONN - CONN HEADER VERT DUAL 14POS 2.54; Item Num: P23-38701R; Manufacturer Part Num: 61301421121
U8-U11 = 824013: DIODE - TVS DIODE, HIGH SPEED SERIES, 3.3VWM 6VC SOT23; Item Num: P08-20832R; Manufacturer: Wurth Elektronik
D3-D8 = LED_WURTH_1: LED - BRIGHT GREEN, VF=2V, IF=0.03A, 0603; Item Num: P09-21344R; LIFECYCLE_PHASE: Active; Lead Free Status: Lead Free; Manufacturer: Wurth Electroniks; Manufacturer Part Num: 150060VS75000; Num Pins: 2; PART_SUBCLASS: LEDS; Part Class: LEDS; RoHS Compliant: RoHS Compliant
D9-D11 = LED_WURTH_1: LED -YELLOW, VF=2V, IF=0.03A, 0603; Item Num: P09-21346R; LIFECYCLE_PHASE: Active; Lead Free Status: Lead Free; Manufacturer: Wurth Electroniks; Manufacturer Part Num: 150060YS75000; Num Pins: 2; PART_SUBCLASS: LEDS; Part Class: LEDS; RoHS Compliant: RoHS Compliant
R183 R186-R188 R193 R200 = R: RES, 150 OHM, 5%, 1/16W, 0402; Item Num: P02-14145R; Lead Free Status: No; Manufacturer: Panasonic; Manufacturer Part Num: ERJ-2GEJ151X; Num Pins: 2; Part Class: Resistors; Price: 0; RoHS Compliant: Yes
R194 R278 = R: RES, 390 Ohms, 5%, 1/16W, 0402; Item Num: P02-14109R; Manufacturer: Panasonic; Manufacturer Part Num: ERJ-2GEJ391X; Num Pins: 2; Part Class: Resistors; Price: 0; RoHS Compliant: Yes
S1-S4 S6 S7 = TS-A02SA-2-S100: SWITCH - PUSHBUTTON, SPST, SMD; Item Num: P11-24535R; Lead Free Status: No; Manufacturer: Wurth Elektronik; Manufacturer Part Num: 430181038816; Num Pins: 4; Part Class: Switches; RoHS Compliant: Yes
SW1 SW2 = SPST4: SWITCHES - 4 POS, 8 PIN, Ultra-mini SMT Half-pitch Slider DIP Switch; AGILE_LINK: http://sj-agile9app/Agile/PLMServlet?action=OpenEmailObject&classid=10000&objid=258073635; Item Num: P11-24098R; LIFECYCLE_PHASE: Preliminary; Lead Free Status: Not Lead Free; MFR_LIFECYCLE: Active; Manufacturer: Wurth Electronik; Manufacturer Part Num: 416131160804; Num Pins: 8; PART_SUBCLASS: SWITCHES; RoHS Compliant: RoHS Compliant

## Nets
1.2V_CORE_POK: U4.Y11(IOB4_36) ; also on sheet 22
1.2V_LED: D11.2(CATHODE) U4.Y9(IOB4_51)
1.2V_LED_R: D11.1(ANODE) R278.2
1.2V_VCCIO: R181.1 R182.1 R184.1 R185.1 R195.1 R196.1 R198.1 R202.1 ; also on sheet 6 10 22 23 24
1.8V: L1.1 L2.1 L3.1 L6.2 ; also on sheet 4 10 11 12 20 21 22 23 24
1.8V_AVDD: C52.1 C53.1 C54.1 C55.1 L3.2 R119.1 U3.15(AVDD) U3.19(AVDD) U3.25(AVDD)
1.8V_DVDD: C44.1 C45.1 C46.1 C47.1 C48.1 L1.2 U3.1(DVDD) U3.11(DVDD) U3.31(DVDD) U3.51(DVDD)
1.8V_PVDD: C49.1 C50.1 C51.1 L2.2 U3.12(PVDD) U3.13(BGVDD)
1.8V_SI5338: C88.1 L6.1 U14.20(VDDO0)
2.5V: C72.1 C73.1 C76.1 C77.1 J12.1 J12.2 J13.1 J13.2 R137.1 R139.1 R200.2 R205.2 U4.C9(VCCIO2) U4.C10(VCCIO2) U4.C11(VCCIO2) U4.D10(VCCIO2) U4.D11(VCCINT) U4.K4(VCCINT) U4.L17(VCCINT) U4.U11(VCCINT) ; also on sheet 9 21 22 23 24
2.5V_LED_R: D10.1(ANODE) R200.1
3.3V: C58.2 C63.1 C64.1 C65.1 C66.1 C67.1 C68.1 C69.1 C70.1 C74.1 C75.1 C78.1 C79.1 C80.1 C81.1 J6.4 J7.4 J8.6 J8.12 J9.6 J9.12 J14.5(IO5) J14.6(IO6) L4.1 L5.2 L9.1 R98.1 R99.1 R100.1 R101.1 R127.1 R128.1 R136.1 R138.1 R140.1 R141.1 R142.1 R145.2 R146.2 R147.1 R183.1 R186.1 R187.1 R188.1 R189.1 R190.1 R191.1 R192.1 R193.1 R194.1 R203.1 R204.1 R248.2 R278.1 U4.J18(VCCIO3) U4.K3(VCCIO1) U4.K17(VCCIO3) U4.K18(VCCIO3) U4.L3(VCCIO1) U4.L4(VCCIO1) U4.L18(VCCIO3) U4.M3(VCCIO1) U4.U10(VCCIO4) U4.V10(VCCIO4) U4.V11(VCCIO4) U4.V12(VCCIO4) U5.4(VCC) U7.3(AVCC) U7.7(AVCC) U7.11(VCC) U7.17(VCC) U7.27(VCC) U7.32(VCC) U7.43(VCC) U7.55(VCC) U8.5(VDD) U9.5(VDD) U10.5(VDD) U11.5(VDD) ; also on sheet 9 11 12 20 22 23 24 25
3.3V_DVDD: C56.1 C57.1 L4.2 R120.2 R121.2 R122.2 U3.29(DVDD_3V)
3.3V_OV5640: C173.1 J3.16 R248.1
3.3V_SI510: C240.1 L9.2 R214.1 U15.6(VDD)
3.3V_SI5338: C82.1 C83.1 C84.1 C85.1 C86.1 L5.1 U14.7(VDD1) U14.11(VDDO3) U14.15(VDDO2) U14.16(VDDO1) U14.24(VDD2)
5V: C42.1 C43.1 D1.8 D2.8 J4.18(5V_VCC) R114.2 R115.2 R199.1 ; also on sheet 20 21 22
5V_LED_R: D9.1(ANODE) R199.2
GND: C37.2 C38.2 C39.2 C40.2 C41.2 C42.2 C43.2 C44.2 C45.2 C46.2 C47.2 C48.2 C49.2 C50.2 C51.2 C52.2 C53.2 C54.2 C55.2 C56.2 C57.2 C58.1 C59.2 C60.2 C61.2 C62.2 C63.2 C64.2 C65.2 C66.2 C67.2 C68.2 C69.2 C70.2 C71.2 C72.2 C73.2 C74.2 C75.2 C76.2 C77.2 C78.2 C79.2 C80.2 C81.2 C82.2 C83.2 C84.2 C85.2 C86.2 C87.1 C88.2 C89.1 C173.2 C240.2 D1.7 D2.7 D9.2(CATHODE) D10.2(CATHODE) J3.3 J3.4 J3.7 J3.10 J3.17 J3.18 J4.2(TMDS_DATA_SHLD2) J4.5(TMDS_DATA_SHLD1) J4.8(TMDS_DATA_SHLD0) J4.11(TMDS_DATA_SHLD_CLK) J4.17(DDC_CEC_GND) J4.G1(MTG1) J4.G2(MTG2) J4.G3(MTG3) J4.G4(MTG4) J5.5(GND) J6.2 J6.10 J7.10 J8.5 J8.11 J9.5 J9.11 J12.7 J12.8 J12.13 J12.14 J12.19 J12.20 J13.7 J13.8 J13.13 J13.14 J13.19 J13.20 J14.11(IO11) J14.12(IO12) R111.1 R112.1 R113.1 R116.1 R117.2 R118.2 R124.2 R125.1 R126.2 R134.1 R135.1 R144.1 R180.1 R269.1 S1.1 S1.2 S2.1 S2.2 S3.1 S3.2 S4.1 S4.2 S6.1 S6.2 S7.1 S7.2 SW1.1(A1) SW1.2(A2) SW1.3(A3) SW1.4(A4) SW2.1(A1) SW2.2(A2) SW2.3(A3) SW2.4(A4) U3.65(EPAD_GND) U4.C8(GNDIO) U4.C12(GNDIO) U4.C13(GNDIO) U4.D9(GNDIO) U4.D12(GNDINT) U4.H3(GNDIO) U4.H18(GNDIO) U4.J3(GNDIO) U4.J4(GNDINT) U4.J17(GNDIO) U4.M4(GNDIO) U4.M17(GNDINT) U4.M18(GNDIO) U4.N3(GNDIO) U4.N18(GNDIO) U4.U9(GNDIO) U4.U12(GNDINT) U4.V8(GNDIO) U4.V9(GNDIO) U4.V13(GNDIO) U5.1(GND) U6.3(GND) U7.6(AGND) U7.10(AGND) U7.12(GND) U7.14(RESERVED) U7.26(GND) U7.28(GND) U7.41(GND) U7.53(GND) U7.56(GND) U7.57(EXPOSED_PAD) U8.2(GND) U9.2(GND) U10.2(GND) U11.2(GND) U14.3(CLKIN) U14.4(I2C_LSB) U14.6(FDBK_N) U14.23(RSVD_GND) U14.25(EPAD) U15.3(GND) Y1.2 Y1.4 Y2.2 Y2.4 ; also on sheet 4 6 8 9 10 11 12 20 21 22 23 24 25
GND_EARTH: C59.1 J5.6(SHELL1) J5.7(SHELL2) J5.8(SHELL3) J5.9(SHELL4) R125.2
VBUS_5V: J5.1(VBUS) R133.1 ; also on sheet 20
24M_XTALIN: C60.1 U7.5(XTALIN) Y1.1
24M_XTALOUT: C61.1 U7.4(XTALOUT) Y1.3
C_USB_MAX_TCK: J6.1 R129.1 R135.2 U4.W2(TCK)
C_USB_MAX_TDI: J6.9 R130.1 U4.U2(TDI)
C_USB_MAX_TDO: J6.3 R131.1 U4.V2(TDO)
C_USB_MAX_TMS: J6.5 R132.1 R136.2 U4.T3(TMS)
CEC_CLK: R111.2 U3.32(CEC_CLK)
CEC_IO: R112.2 U3.30(CEC)
CLK24M: R213.2 ; also on sheet 8
CLK24M_R: R213.1 U14.22(CLK0A)
CLK50M_EN: R214.2 U15.2(OE)
CLK50M_MAX10: R215.2 ; also on sheet 8
CLK50M_MAX10_R: R215.1 U15.4(CLKp)
CLK50M_MAXII: R216.2 U4.L1(IOB1/GCLK1)
CLK50M_MAXII_R: R216.1 U15.5(CLKn)
CLK100M_LPDDR2: R208.2 ; also on sheet 8
CLK100M_LPDDR2_BK: R207.2 ; also on sheet 8
CLK100M_LPDDR2_BK_R: R207.1 U14.9(CLK3B)
CLK100M_LPDDR2_R: R208.1 U14.10(CLK3A)
CLK125M: R210.2 ; also on sheet 8
CLK125M_R: R210.1 U14.13(CLK2B)
CLKOUT_LVDS_N: J12.18 R170.1 ; also on sheet 8
CLKOUT_LVDS_P: J12.16 R170.2 ; also on sheet 8
EXT_JTAG_TCK: R143.1 R144.2 R148.2 U4.M20(IOB3/GCLK2)
EXT_JTAG_TCK_R: J7.1 R148.1
EXT_JTAG_TDI: R146.1 R152.2 U4.H17(IOB3_21)
EXT_JTAG_TDI_R: J7.9 R152.1
EXT_JTAG_TDO: R149.2 U4.F17(IOB3_13)
EXT_JTAG_TDO_R: J7.3 R149.1
EXT_JTAG_TMS: R145.1 R150.2 U4.G17(IOB3_17)
EXT_JTAG_TMS_R: J7.5 R150.1
FLASH_RESETn: R249.1 ; also on sheet 7 25
FLASH_RESETn_MAXII: R249.2 U4.U14(IOB4_2)
FX2_D_N: J5.2(D-) U6.2(D-) U7.9(DMINUS)
FX2_D_P: J5.3(D+) U6.1(D+) U7.8(DPLUS)
FX2_FLAGA: U4.H4(IOB1_24) U7.29(CTL0)
FX2_FLAGB: U4.H1(IOB1_22) U7.30(CTL1)
FX2_FLAGC: U4.J1(IOB1_25) U7.31(CTL2)
FX2_PA0: U4.N4(IOB1_33) U7.33(PA0)
FX2_PA1: U4.P4(IOB1_37) U7.34(PA1)
FX2_PA2: U4.R4(IOB1_41) U7.35(PA2)
FX2_PA3: U4.T4(IOB1_44) U7.36(PA3)
FX2_PA4: U4.M1(IOB1_29) U7.37(PA4)
FX2_PA5: U4.N1(IOB1_31) U7.38(PA5)
FX2_PA6: U4.P1(IOB1_34) U7.39(PA6)
FX2_PA7: U4.R1(IOB1_38) U7.40(PA7)
FX2_PB0: U4.D1(IOB1_6) U7.18(PB0)
FX2_PB1: U4.E1(IOB1_10) U7.19(PB1)
FX2_PB2: U4.F1(IOB1_14) U7.20(PB2)
FX2_PB3: U4.G1(IOB1_18) U7.21(PB3)
FX2_PB4: U4.D4(IOB1_9) U7.22(PB4)
FX2_PB5: U4.E4(IOB1_13) U7.23(PB5)
FX2_PB6: U4.F4(IOB1_17) U7.24(PB6)
FX2_PB7: U4.G4(IOB1_21) U7.25(PB7)
FX2_PD0: R129.2 U7.45(PD0)
FX2_PD1: R132.2 U7.46(PD1)
FX2_PD2: R130.2 U7.47(PD2)
FX2_PD3: R131.2 U7.48(PD3)
FX2_PD4: U4.Y3(IOB4_45) U7.49(PD4)
FX2_PD5: U4.Y2(IOB4_44) U7.50(PD5)
FX2_PD6: U4.Y4(IOB4_46) U7.51(PD6)
FX2_PD7: U4.Y5(IOB4_47) U7.52(PD7)
FX2_RESETn: R126.1 U4.Y13(IOB4/DEV_CLRn) U5.2(~{RESET}) U7.42(~{RESET})
FX2_SCL: R127.2 U4.B1(IOB1_1) U7.15(SCL)
FX2_SDA: R123.1 R128.2 U7.16(SDA)
FX2_SLRDn: U4.Y6(IOB4_48) U7.1(RDY0)
FX2_SLWRn: U4.Y7(IOB4_49) U7.2(RDY1)
FX2_WAKEUP: C62.1 R133.2 R134.2 U7.44(WAKEUP)
HDMI_DDCSCL: D2.5 J4.15(SCL) R115.1 U3.33(DDCSCL)
HDMI_DDCSDA: D2.6 J4.16(SDA) R114.1 U3.34(DDCSDA)
HDMI_HPD: D1.5 J4.19(HOT_PLUG_DETECT) R117.1 U3.16(HPD)
HDMI_HSYNC: U3.64(HSYNC) ; also on sheet 7
HDMI_INTR: R122.1 U3.28(INT) ; also on sheet 7
HDMI_IREF: R116.2 U3.14(R_EXT)
HDMI_SCL: R121.1 U3.35(SCL) ; also on sheet 7
HDMI_SDA: R120.1 U3.36(SDA) ; also on sheet 7
HDMI_VIDEO_CLK: R113.2 U3.53(CLK) ; also on sheet 8
HDMI_VIDEO_DATA_EN: U3.63(DE) ; also on sheet 7
HDMI_VIDEO_DIN0: U3.62(D0) ; also on sheet 7
HDMI_VIDEO_DIN1: U3.61(D1) ; also on sheet 7
HDMI_VIDEO_DIN2: U3.60(D2) ; also on sheet 7
HDMI_VIDEO_DIN3: U3.59(D3) ; also on sheet 7
HDMI_VIDEO_DIN4: U3.58(D4) ; also on sheet 7
HDMI_VIDEO_DIN5: U3.57(D5) ; also on sheet 7
HDMI_VIDEO_DIN6: U3.56(D6) ; also on sheet 7
HDMI_VIDEO_DIN7: U3.55(D7) ; also on sheet 7
HDMI_VIDEO_DIN8: U3.54(D8) ; also on sheet 7
HDMI_VIDEO_DIN9: U3.52(D9) ; also on sheet 7
HDMI_VIDEO_DIN10: U3.50(D10) ; also on sheet 7
HDMI_VIDEO_DIN11: U3.49(D11) ; also on sheet 7
HDMI_VIDEO_DIN12: U3.48(D12) ; also on sheet 7
HDMI_VIDEO_DIN13: U3.47(D13) ; also on sheet 7
HDMI_VIDEO_DIN14: U3.46(D14) ; also on sheet 7
HDMI_VIDEO_DIN15: U3.45(D15) ; also on sheet 7
HDMI_VIDEO_DIN16: U3.44(D16) ; also on sheet 7
HDMI_VIDEO_DIN17: U3.43(D17) ; also on sheet 7
HDMI_VIDEO_DIN18: U3.42(D18) ; also on sheet 7
HDMI_VIDEO_DIN19: U3.41(D19) ; also on sheet 7
HDMI_VIDEO_DIN20: U3.40(D20) ; also on sheet 7
HDMI_VIDEO_DIN21: U3.39(D21) ; also on sheet 7
HDMI_VIDEO_DIN22: U3.38(D22) ; also on sheet 7
HDMI_VIDEO_DIN23: U3.37(D23) ; also on sheet 7
HDMI_VSYNC: U3.2(VSYNC) ; also on sheet 7
I2C_MAXII_SCL: R139.2 R206.1 U4.A7(IOB2_18)
I2C_MAXII_SDA: R137.2 R209.1 U4.A6(IOB2_17)
JTAG_LOCK: R151.2 U4.Y8(IOB4_50)
JTAG_LOCK_R: J7.7 R151.1
JTAG_SAFE: U4.Y17(IOB4_41) ; also on sheet 4
MAX10_BYPASSn: R192.2 SW2.5(B4) U4.B20(IOB3_1)
MAX10_CONF_DONE: U4.U13(IOB4_1) ; also on sheet 9
MAX10_CONFIG_SEL: R191.2 SW2.6(B3) ; also on sheet 9
MAX10_JTAG_TCK: U4.A15(IOB2_7) ; also on sheet 9
MAX10_JTAG_TDI: U4.A13(IOB2_5) ; also on sheet 9
MAX10_JTAG_TDO: U4.A12(IOB2_4) ; also on sheet 9
MAX10_JTAG_TMS: U4.A16(IOB2_8) ; also on sheet 9
MAX10_JTAGEN: U4.A14(IOB2_6) ; also on sheet 9
MAX10_nCONFIG: R203.2 S6.3 S6.4 ; also on sheet 9
MAX10_nSTATUS: U4.U16(IOB4_4) ; also on sheet 9
MAX10_RESETn: R204.2 S7.3 S7.4 ; also on sheet 9
MAX_SDA: R123.2 U4.C1(IOB1_2)
MAXII_CONF_DONE: D8.2(CATHODE) U4.Y10(IOB4_35)
MAXII_CONF_DONE_R: D8.1(ANODE) R194.2
MIPI_TX_CLK24MHz: R212.2 ; also on sheet 11
MIPI_TX_CLK24MHz_R: R212.1 U14.21(CLK0B)
OV5640_CAM_PWRON: C38.1 J3.11 R98.2 ; also on sheet 4
OV5640_CAM_RESETB: C39.1 J3.15 R99.2 ; also on sheet 4
OV5640_CLK24MHz: J3.12 R211.2
OV5640_CLK24MHz_R: R211.1 U14.18(CLK1A)
OV5640_CLK_HS_N: J3.5 R97.1 R102.1 ; also on sheet 8
OV5640_CLK_HS_P: J3.6 R95.1 R96.2 ; also on sheet 8
OV5640_CLK_LP_N: R102.2 ; also on sheet 6
OV5640_CLK_LP_P: R95.2 ; also on sheet 6
OV5640_DATA_HS_N1: J3.8 R105.1 R106.1 ; also on sheet 5
OV5640_DATA_HS_N2: J3.1 R109.1 R110.1 ; also on sheet 5
OV5640_DATA_HS_P1: J3.9 R103.1 R104.2 ; also on sheet 5
OV5640_DATA_HS_P2: J3.2 R107.1 R108.2 ; also on sheet 5
OV5640_DATA_LP_N1: R106.2 ; also on sheet 6
OV5640_DATA_LP_N2: R110.2 ; also on sheet 6
OV5640_DATA_LP_P1: R103.2 ; also on sheet 6
OV5640_DATA_LP_P2: R107.2 ; also on sheet 6
OV5640_SDA: J3.14 R100.2 ; also on sheet 4
OV5640_SDC: J3.13 R101.2 ; also on sheet 4
PMODA_D0: R156.1 ; also on sheet 7
PMODA_D1: R157.1 ; also on sheet 7
PMODA_D2: R160.1 ; also on sheet 7
PMODA_D3: R163.1 ; also on sheet 7
PMODA_D4: R158.2 ; also on sheet 7
PMODA_D5: R159.2 ; also on sheet 7
PMODA_D6: R161.2 ; also on sheet 7
PMODA_D7: R164.2 ; also on sheet 7
PMODA_IO0: J8.1 R156.2 U9.3(IO2)
PMODA_IO1: J8.2 R157.2 U9.4(IO3)
PMODA_IO2: J8.3 R160.2 U8.6(IO4)
PMODA_IO3: J8.4 R163.2 U8.1(IO1)
PMODA_IO4: J8.7 R158.1 U9.1(IO1)
PMODA_IO5: J8.8 R159.1 U9.6(IO4)
PMODA_IO6: J8.9 R161.1 U8.4(IO3)
PMODA_IO7: J8.10 R164.1 U8.3(IO2)
PMODB_D0: R171.1 ; also on sheet 7
PMODB_D1: R173.1 ; also on sheet 7
PMODB_D2: R175.1 ; also on sheet 7
PMODB_D3: R177.1 ; also on sheet 7
PMODB_D4: R172.2 ; also on sheet 7
PMODB_D5: R174.2 ; also on sheet 7
PMODB_D6: R176.2 ; also on sheet 7
PMODB_D7: R178.2 ; also on sheet 7
PMODB_IO0: J9.1 R171.2 U10.1(IO1)
PMODB_IO1: J9.2 R173.2 U10.3(IO2)
PMODB_IO2: J9.3 R175.2 U10.6(IO4)
PMODB_IO3: J9.4 R177.2 U11.6(IO4)
PMODB_IO4: J9.7 R172.1 U10.4(IO3)
PMODB_IO5: J9.8 R174.1 U11.3(IO2)
PMODB_IO6: J9.9 R176.1 U11.1(IO1)
PMODB_IO7: J9.10 R178.1 U11.4(IO3)
SI5338_INTR: R205.1 U4.A1(IOB2_1) U14.8(INTR)
Si5338A_XTAL_25M_N: C89.2 U14.2(CLKIN_N) Y2.1
Si5338A_XTAL_25M_P: C87.2 U14.1(CLKIN_P) Y2.3
TMDS_CLK_N: D1.1 J4.12(TMDS_CLK_N) U3.17(TXC-)
TMDS_CLK_P: D1.2 J4.10(TMDS_CLK_P) U3.18(TXC+)
TMDS_DATA_N0: D1.3 J4.9(TMDS_DATA_N0) U3.20(TX0-)
TMDS_DATA_N1: D2.1 J4.6(TMDS_DATA_N1) U3.23(TX1-)
TMDS_DATA_N2: D2.3 J4.3(TMDS_DATA_N2) U3.26(TX2-)
TMDS_DATA_P0: D1.4 J4.7(TMDS_DATA_P0) U3.21(TX0+)
TMDS_DATA_P1: D2.2 J4.4(TMDS_DATA_P1) U3.24(TX1+)
TMDS_DATA_P2: D2.4 J4.1(TMDS_DATA_P2) U3.27(TX2+)
USB_ADDR0: U4.R20(IOB3_40) ; also on sheet 4
USB_ADDR1: U4.J20(IOB3_25) ; also on sheet 4
USB_CLK: U4.K1(IOB1/GCLK0) U7.13(IFCLK) ; also on sheet 8
USB_DATA0: U4.H20(IOB3_23) ; also on sheet 4
USB_DATA1: U4.T20(IOB3_44) ; also on sheet 4
USB_DATA2: U4.E20(IOB3_12) ; also on sheet 4
USB_DATA3: U4.P20(IOB3_36) ; also on sheet 4
USB_DATA4: U4.V20(IOB3_50) ; also on sheet 4
USB_DATA5: U4.W20(IOB3_52) ; also on sheet 4
USB_DATA6: U4.K20(IOB3_27) ; also on sheet 4
USB_DATA7: U4.Y20(IOB3_53) ; also on sheet 4
USB_DISABLEn: J7.2 R147.2 U4.E17(IOB3_9)
USB_EMPTY: R138.2 U4.G20(IOB3_20) ; also on sheet 4
USB_FULL: R142.2 U4.F20(IOB3_16) ; also on sheet 4
USB_OEn: U4.U20(IOB3_48) ; also on sheet 4
USB_RDn: U4.L20(IOB3/GCLK3) ; also on sheet 4
USB_RESETn: U4.Y18(IOB4_42) ; also on sheet 4
USB_SCL: R140.2 U4.D20(IOB3_8) ; also on sheet 4
USB_SDA: R141.2 U4.C20(IOB3_4) ; also on sheet 4
USB_WRn: U4.Y19(IOB4_43) ; also on sheet 4
USER_CLKIN_IO_N: J12.5 R268.1
USER_CLKIN_IO_P: J12.3 R179.1
USER_CLKIN_N_MAX10: R268.2 R269.2 R272.1 ; also on sheet 8
USER_CLKIN_P: R179.2 R180.2 R272.2 ; also on sheet 8
USER_DIPSW0: R181.2 SW1.8(B1) ; also on sheet 6
USER_DIPSW1: R182.2 SW1.7(B2) ; also on sheet 6
USER_DIPSW2: R184.2 SW1.6(B3) ; also on sheet 6
USER_DIPSW3: R185.2 SW1.5(B4) ; also on sheet 6
USER_DIPSW4: R189.2 SW2.8(B1) ; also on sheet 4
USER_DIPSW5: R190.2 SW2.7(B2) ; also on sheet 4
USER_IO0: J14.1(IO1) ; also on sheet 7
USER_IO1: J14.3(IO3) ; also on sheet 7
USER_IO2: J14.7(IO7) ; also on sheet 7
USER_IO3: J14.9(IO9) ; also on sheet 7
USER_IO4: J14.13(IO13) ; also on sheet 7
USER_IO5: J14.2(IO2) ; also on sheet 7
USER_IO6: J14.4(IO4) ; also on sheet 7
USER_IO7: J14.8(IO8) ; also on sheet 7
USER_IO8: J14.10(IO10) ; also on sheet 7
USER_IO9: J14.14(IO14) ; also on sheet 7
USER_LED0: D3.2(CATHODE) ; also on sheet 7
USER_LED0_R: D3.1(ANODE) R183.2
USER_LED1: D4.2(CATHODE) ; also on sheet 7
USER_LED1_R: D4.1(ANODE) R186.2
USER_LED2: D5.2(CATHODE) ; also on sheet 7
USER_LED2_R: D5.1(ANODE) R187.2
USER_LED3: D6.2(CATHODE) ; also on sheet 7
USER_LED3_R: D6.1(ANODE) R188.2
USER_LED4: D7.2(CATHODE) ; also on sheet 7
USER_LED4_R: D7.1(ANODE) R193.2
USER_LVDS_N0: J12.11 R153.1 ; also on sheet 5
USER_LVDS_N1: J12.17 R154.1 ; also on sheet 5
USER_LVDS_N2: J12.6 R155.1 ; also on sheet 5
USER_LVDS_N3: J12.12 R162.1 ; also on sheet 5
USER_LVDS_N4: J13.12 R165.1 ; also on sheet 5
USER_LVDS_N5: J13.5 R166.1 ; also on sheet 5
USER_LVDS_N6: J13.11 R167.1 ; also on sheet 5
USER_LVDS_N7: J13.17 R168.1 ; also on sheet 5
USER_LVDS_N8: J13.6 R169.1 ; also on sheet 5
USER_LVDS_P0: J12.9 R153.2 ; also on sheet 5
USER_LVDS_P1: J12.15 R154.2 ; also on sheet 5
USER_LVDS_P2: J12.4 R155.2 ; also on sheet 5
USER_LVDS_P3: J12.10 R162.2 ; also on sheet 5
USER_LVDS_P4: J13.10 R165.2 ; also on sheet 5
USER_LVDS_P5: J13.3 R166.2 ; also on sheet 5
USER_LVDS_P6: J13.9 R167.2 ; also on sheet 5
USER_LVDS_P7: J13.15 R168.2 ; also on sheet 5
USER_LVDS_P8: J13.4 R169.2 ; also on sheet 5
USER_PB0: R202.2 S1.3 S1.4 ; also on sheet 6
USER_PB1: R196.2 S2.3 S2.4 ; also on sheet 6
USER_PB2: R195.2 S3.3 S3.4 ; also on sheet 6
USER_PB3: R198.2 S4.3 S4.4 ; also on sheet 6
N31901: R118.1 R119.2 U3.22(PD)
N16765826: J5.4(ID) R124.1
N16772990: C71.1 R143.2
N16895577: R206.2 U14.12(SCL)
N16895579: R209.2 U14.19(SDA)
N17606282: C37.1 R96.1 R97.2
N17606316: C40.1 R104.1 R105.2
N17606350: C41.1 R108.1 R109.2

Not connected (* = marked no-connect by the designer): D1 6*; J4 13(CEC)* 14(RESERVED_NC)*; J6 6* 7* 8*; J7 6* 8*; J13 16* 18*; U3 3(SPDIF)* 4(MCLK)* 5(I2S0)* 6(I2S1)* 7(I2S2)* 8(I2S3)* 9(SCLK)* 10(LRCLK)*; U4 A2(IOB2_12) A3(IOB2_14) A4(IOB2_15) A5(IOB2_16) A8(IOB2_19) A9(IOB2_20) A10(IOB2_2) A11(IOB2_3) A17(IOB2_9) A18(IOB2_10) A19(IOB2_11) A20(IOB2_13) B2(IOB2_31) B3(IOB2_32) B4(IOB2_33) B5(IOB2_34) B6(IOB2_35) B7(IOB2_36) B8(IOB2_37) B9(IOB2_38) B10(IOB2_21) B11(IOB2_22) B12(IOB2_23) B13(IOB2_24) B14(IOB2_25) B15(IOB2_26) B16(IOB2_27) B17(IOB2_28) B18(IOB2_29) B19(IOB2_30) C2(IOB1_3)* C3(IOB1_4) C4(IOB1_5) C5(IOB2_43) C6(IOB2_44) C7(IOB2_45) C14(IOB2_39) C15(IOB2_40) C16(IOB2_41) C17(IOB2_42) C18(IOB3_2) C19(IOB3_3)* D2(IOB1_7) D3(IOB1_8) D5(IOB2_50) D6(IOB2_51) D7(IOB2_52) D8(IOB2_53) D13(IOB2_46) D14(IOB2_47) D15(IOB2_48) D16(IOB2_49) D17(IOB3_5)* D18(IOB3_6)* D19(IOB3_7) E2(IOB1_11) E3(IOB1_12) E18(IOB3_10) E19(IOB3_11) F2(IOB1_15) F3(IOB1_16) F18(IOB3_14) F19(IOB3_15) G2(IOB1_19) G3(IOB1_20) G18(IOB3_18) G19(IOB3_19)* H2(IOB1_23)* H19(IOB3_22) J2(IOB1_26) J19(IOB3_24)* K2(IOB1_27) K19(IOB3_26) L2(IOB1_28) L19(IOB3_28)* M2(IOB1_30) M19(IOB3_29)* N2(IOB1_32)* N17(IOB3_30) N19(IOB3_31) N20(IOB3_32)* P2(IOB1_35) P3(IOB1_36) P17(IOB3_33)* P18(IOB3_34) P19(IOB3_35) R2(IOB1_39)* R3(IOB1_40) R17(IOB3_37)* R18(IOB3_38) R19(IOB3_39) T1(IOB1_42) T2(IOB1_43) T17(IOB3_41) T18(IOB3_42) T19(IOB3_43)* U1(IOB1_45) U3(IOB1_46) U4(IOB4_5) U5(IOB4_6) U6(IOB4_7) U7(IOB4_8) U8(IOB4_9) U15(IOB4_3) U17(IOB3_45) U18(IOB3_46) U19(IOB3_47) V1(IOB1_47) V3(IOB1_48) V4(IOB4_15) V5(IOB4_16) V6(IOB4_17) V7(IOB4_18) V14(IOB4_10) V15(IOB4_11) V16(IOB4_12) V17(IOB4_13) V18(IOB4_14) V19(IOB3_49) W1(IOB1_49) W3(IOB4_27)* W4(IOB4_28) W5(IOB4_29) W6(IOB4_30) W7(IOB4_31) W8(IOB4_32) W9(IOB4_33) W10(IOB4_19) W11(IOB4_20) W12(IOB4/DEV_OE)* W13(IOB4_21) W14(IOB4_22) W15(IOB4_23) W16(IOB4_24) W17(IOB4_25)* W18(IOB4_26)* W19(IOB3_51) Y1(IOB4_34)* Y12(IOB4_37) Y14(IOB4_38) Y15(IOB4_39) Y16(IOB4_40); U5 3(~{MR})*; U7 54(CLKOUT)*; U14 5(FDBK_P)* 14(CLK2A)* 17(CLK1B)*; U15 1(NC)*

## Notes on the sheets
sheet 13
- MIPI CSI-2 RX D-PHY OV5640
- CAD Note:
  Place resistors near FPGA side.
- OV5640 CSI-2 RX Interface
- CAD Note:
  Place resistors near FPGA side.
- CAD Note:
  Place near J3 connector.
- CAD Note:
  Place resistors near FPGA side.
sheet 14
- HDMI (VIDEO ONLY)
- HDMI TX
- HDMI Power Decoupling
- Note:
  Place 0.1uF capacitor near ADV7513 DVDD pins
- Note:
  Place 0.1uF capacitor near ADV7513 PVDD and BGVDD pin
- Note:
  Place 0.1uF capacitor near ADV7513 AVDD pins
- Note:
  Place 0.1uF capacitor near ADV7513 DVDD_3V pin
- Altera Corporation, 301, Bibo Rd #888, Shanghai, China, 201203
- Copyright (c) 2015, Altera Corporation. All Rights Reserved.
sheet 15
- ON-BOARD USB BLASTER II-1
- USB Blaster II
- ( VCCIO = 3.3V )
- Si510
- Configuration
- IFCLK = 48MHz
- Flash
- JTAG Interface
- ( VCCIO = 3.3V )
- EN5339
- Note:
  Place 0.1uF capacitors near CY7C68013A.
- Altera Corporation, 301, Bibo Rd #888, Shanghai, China, 201203
- Copyright (c) 2015, Altera Corporation. All Rights Reserved.
sheet 16
- ON-BOARD USB BLASTER II-2
- MAX10 USB Interface
- ( VCCIO = 3.3V )
- ( VCCIO = 2.5V )
- JTAG Interface
- MAX II Decoupling
- Note:
  Place decoupling capacitors near MAXII
- USB Blaster Programming Header
- (uses JTAG mode only)
- Altera Corporation, 301, Bibo Rd #888, Shanghai, China, 201203
- Copyright (c) 2015, Altera Corporation. All Rights Reserved.
sheet 17
- PMOD, GPIO, LVDS USER IO
- LVDS Termination
- PMOD
- Note: Place near MAX 10 side.
- PMOD
- User LVDS IO
- LVDS
- User IO
- User LVDS IO
- User GPIO
- Note: USER_CLKIN_IO_P
  is used if external single-ended
  clk needs to use on-chip PLL
  resource.
  USER_CLKIN_IO_P/N is used
  for external differential clk input.
  Values of R179,R180,R268,
  and R269 might be adjusted
  according to user input voltage.
- Altera Corporation, 301, Bibo Rd #888, Shanghai, China, 201203
- Copyright (c) 2015, Altera Corporation. All Rights Reserved.
sheet 18
- PUSHBUTTON, SWITCH, LED
- User DIP Switch
- User LED
- USER DIPSWITCH
- MAXII
- User LED
- ON = 0
- OFF = 1
- BOARD SETTINGS DIPSWITCH
- User Pushbutton
- Logic 0 = Device JTAG Bypass
  Logic 1 = Device JTAG Enable
- ON = 0
- OFF = 1
- Note: MAX10_BYPASSn is used to bypass
  the virtual JTAG device provided within the
  On-Board USB-Blaster II.
- User DIP Switch
- User Pushbutton
- Power LED
- Altera Corporation, 301, Bibo Rd #888, Shanghai, China, 201203
- Copyright (c) 2015, Altera Corporation. All Rights Reserved.
sheet 19
- CLOCKING
- Programmable Clock
- MAX 10
- 3.3V CMOS complimentary
- 3.3V Single-Ended CMOS
- 3.3V Single-Ended CMOS
- 1.8V CMOS complimentary
- MAXII
- Notes:
  Use Clock Control GUI to program Si5338 oscillator outputs.
  (Defaults 100MHz, 125MHz, 24MHz, 24MHz)
  I2C Address 70 HEX
- DM385 CSI-2 TX Interface
- 3.3V CMOS
- 3.3V CMOS
- Altera Corporation, 301, Bibo Rd #888, Shanghai, China, 201203
- Copyright (c) 2015, Altera Corporation. All Rights Reserved.
